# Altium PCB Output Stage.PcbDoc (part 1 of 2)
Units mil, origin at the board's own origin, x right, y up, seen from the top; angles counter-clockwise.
Board outline 5000 x 8750 mil, 6 copper layers (Top Layer, Layer 1, Layer 2, Layer 3, Layer 4, Bottom Layer), stack 91 mil thick; 55 components, 34 nets, 272 pads, 65 vias.
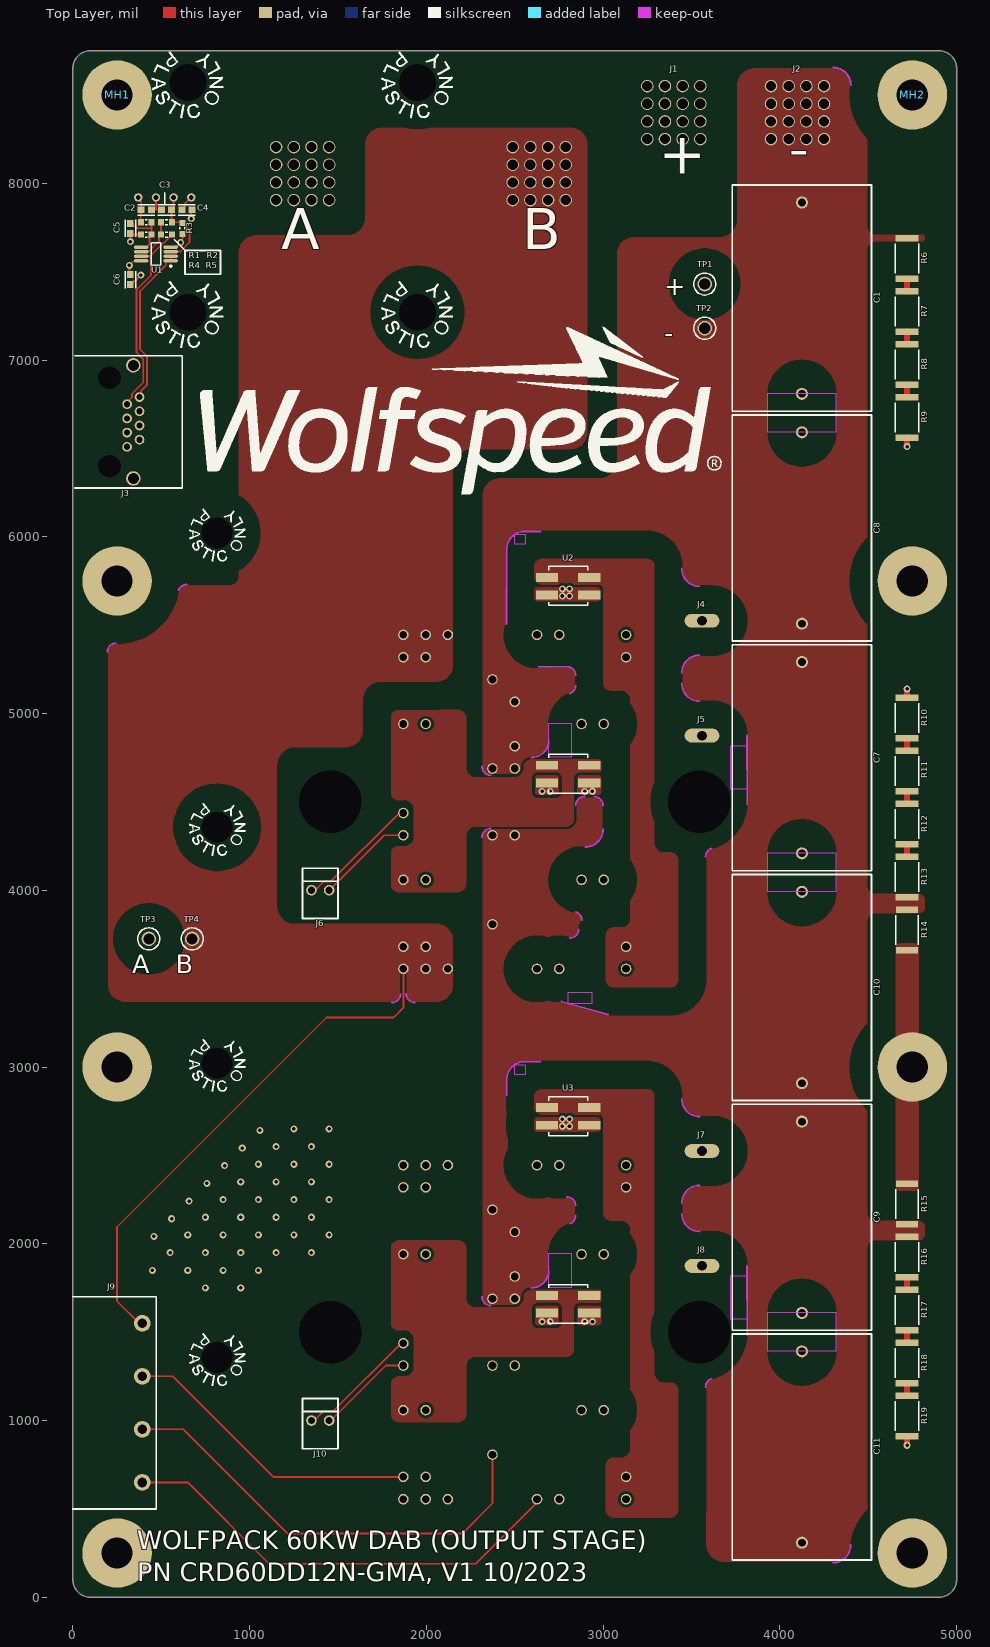
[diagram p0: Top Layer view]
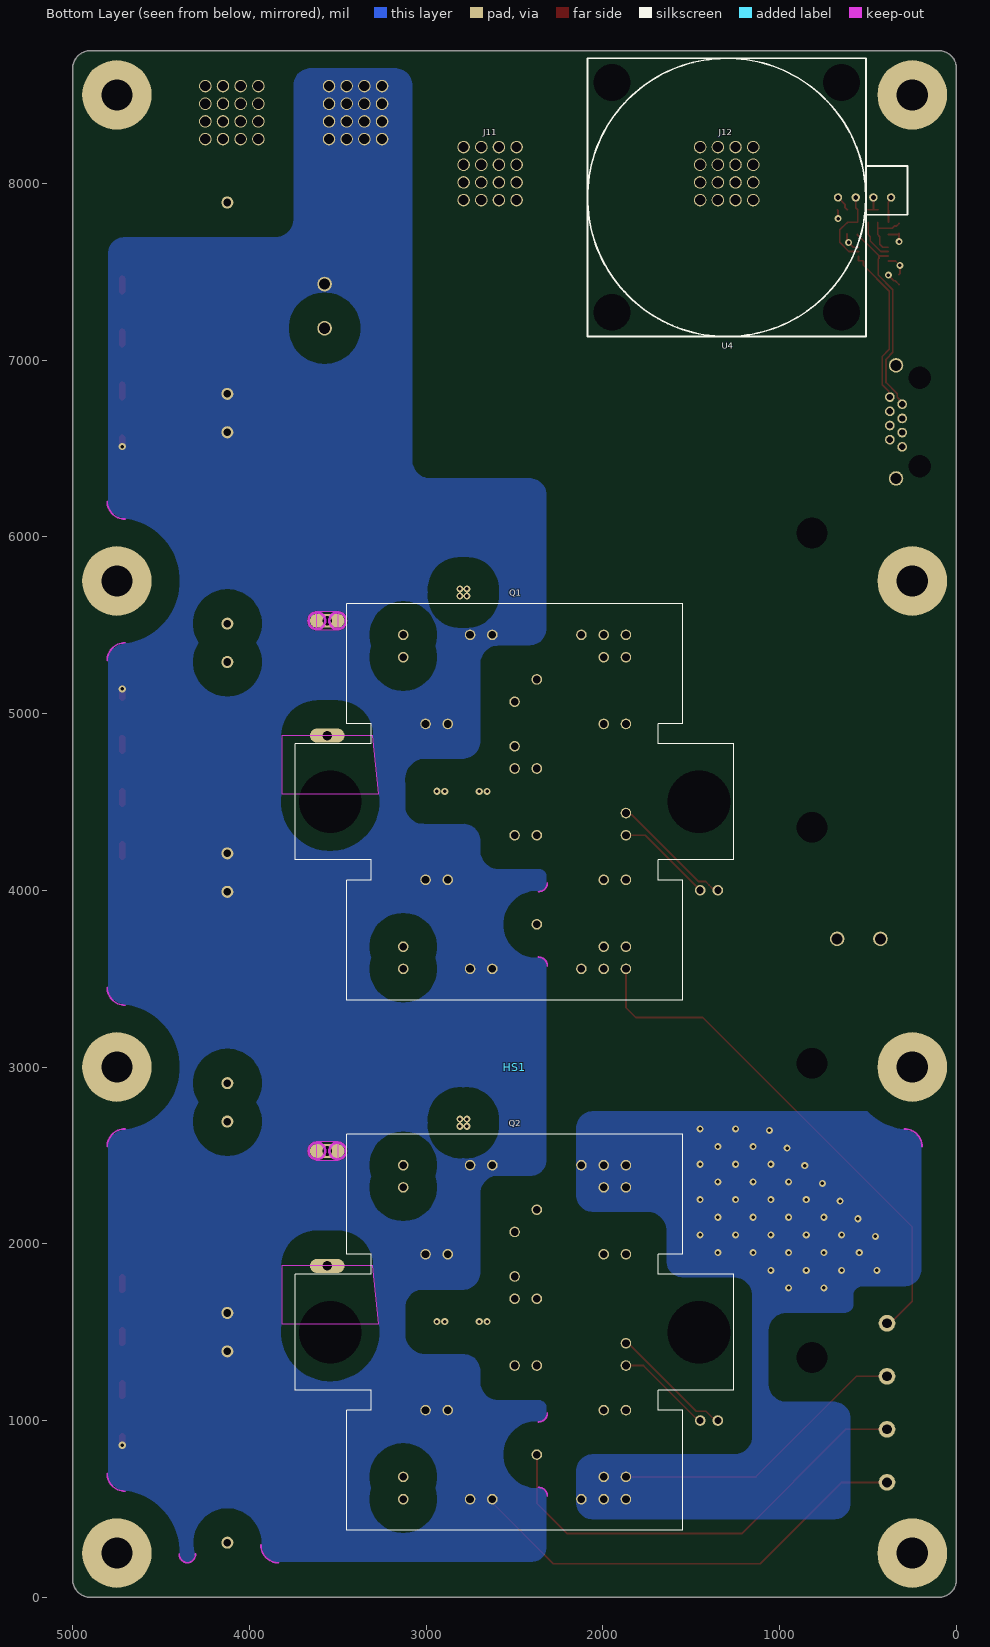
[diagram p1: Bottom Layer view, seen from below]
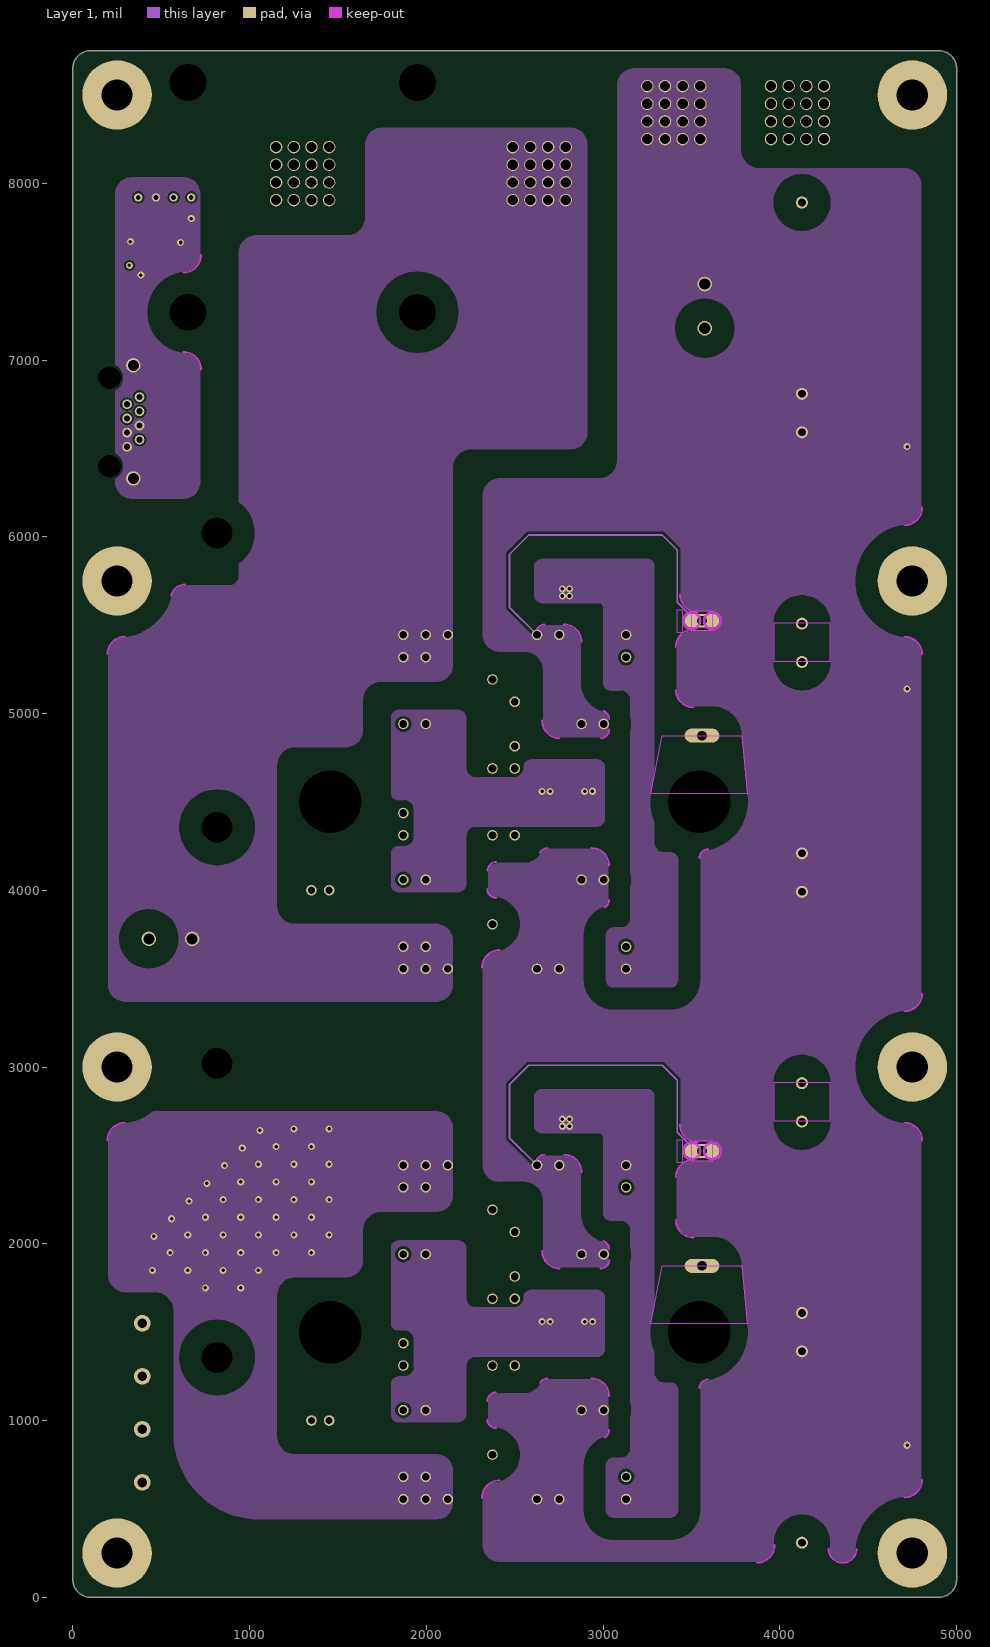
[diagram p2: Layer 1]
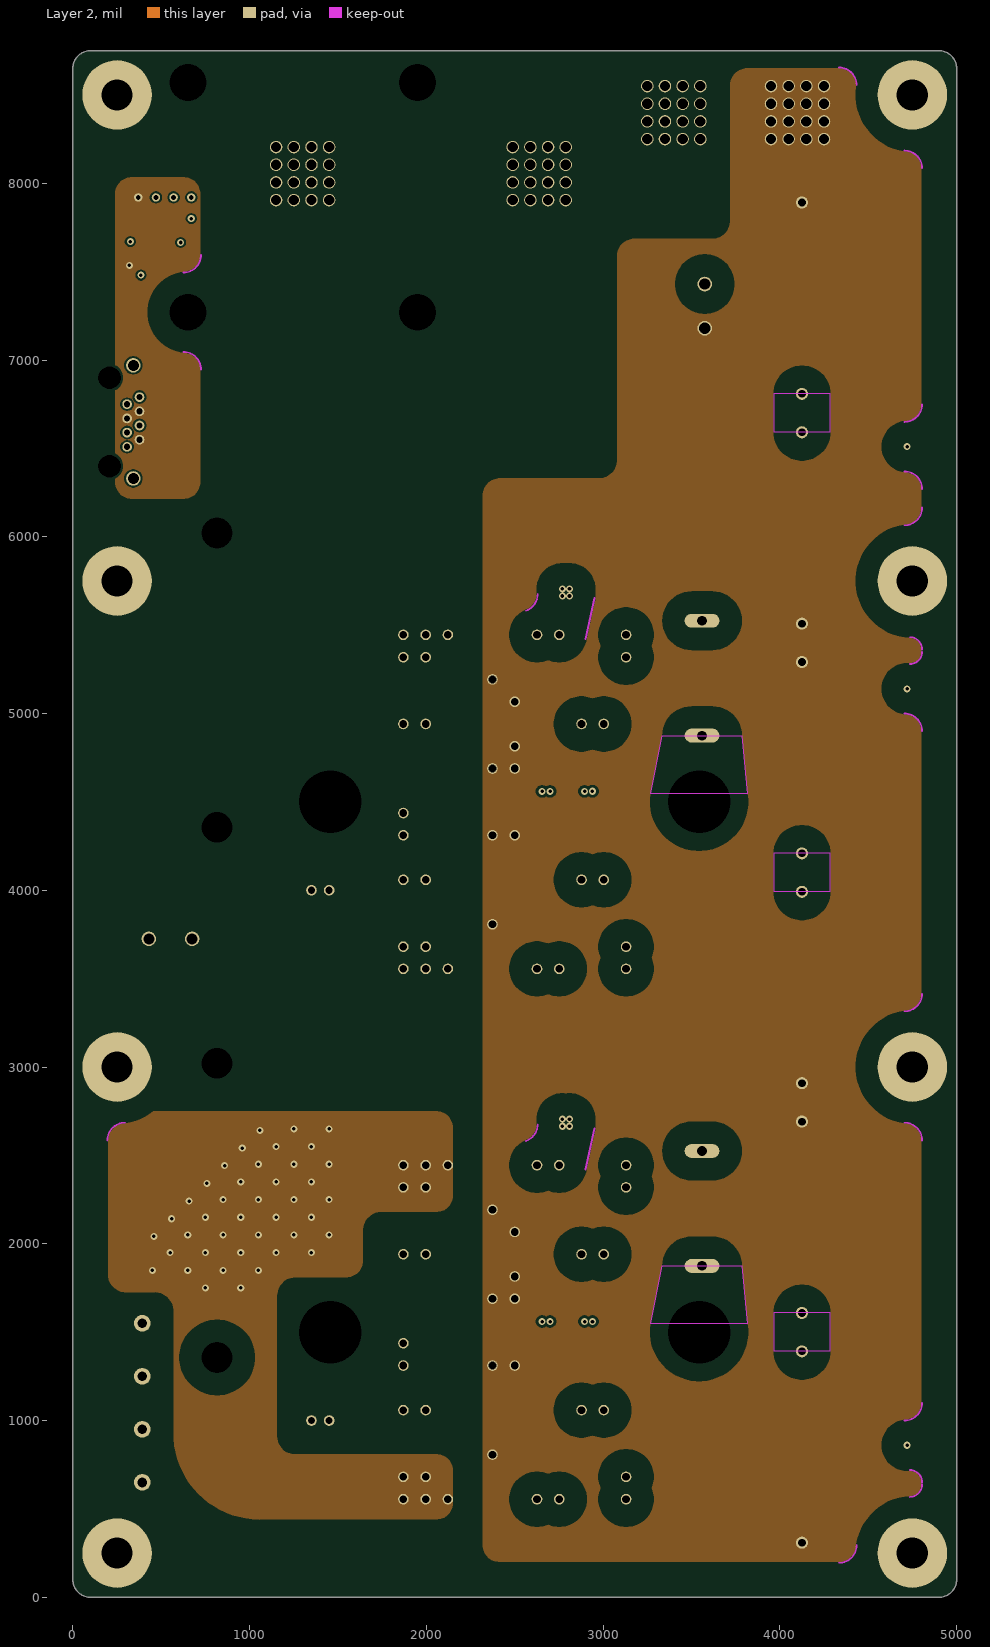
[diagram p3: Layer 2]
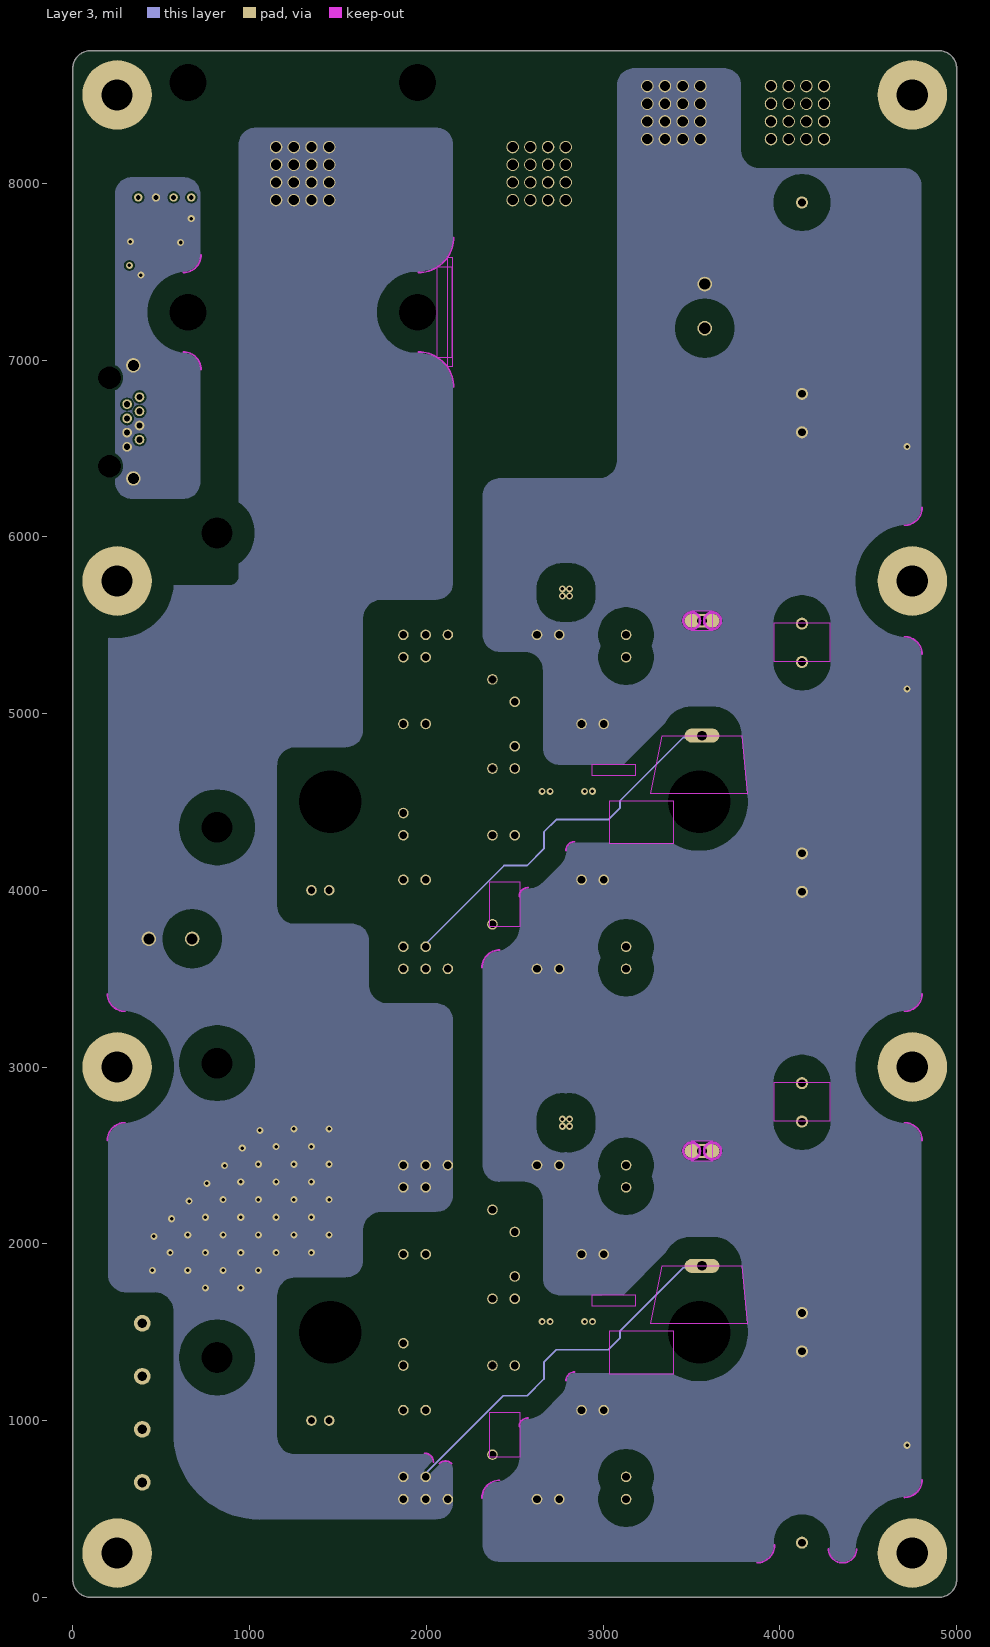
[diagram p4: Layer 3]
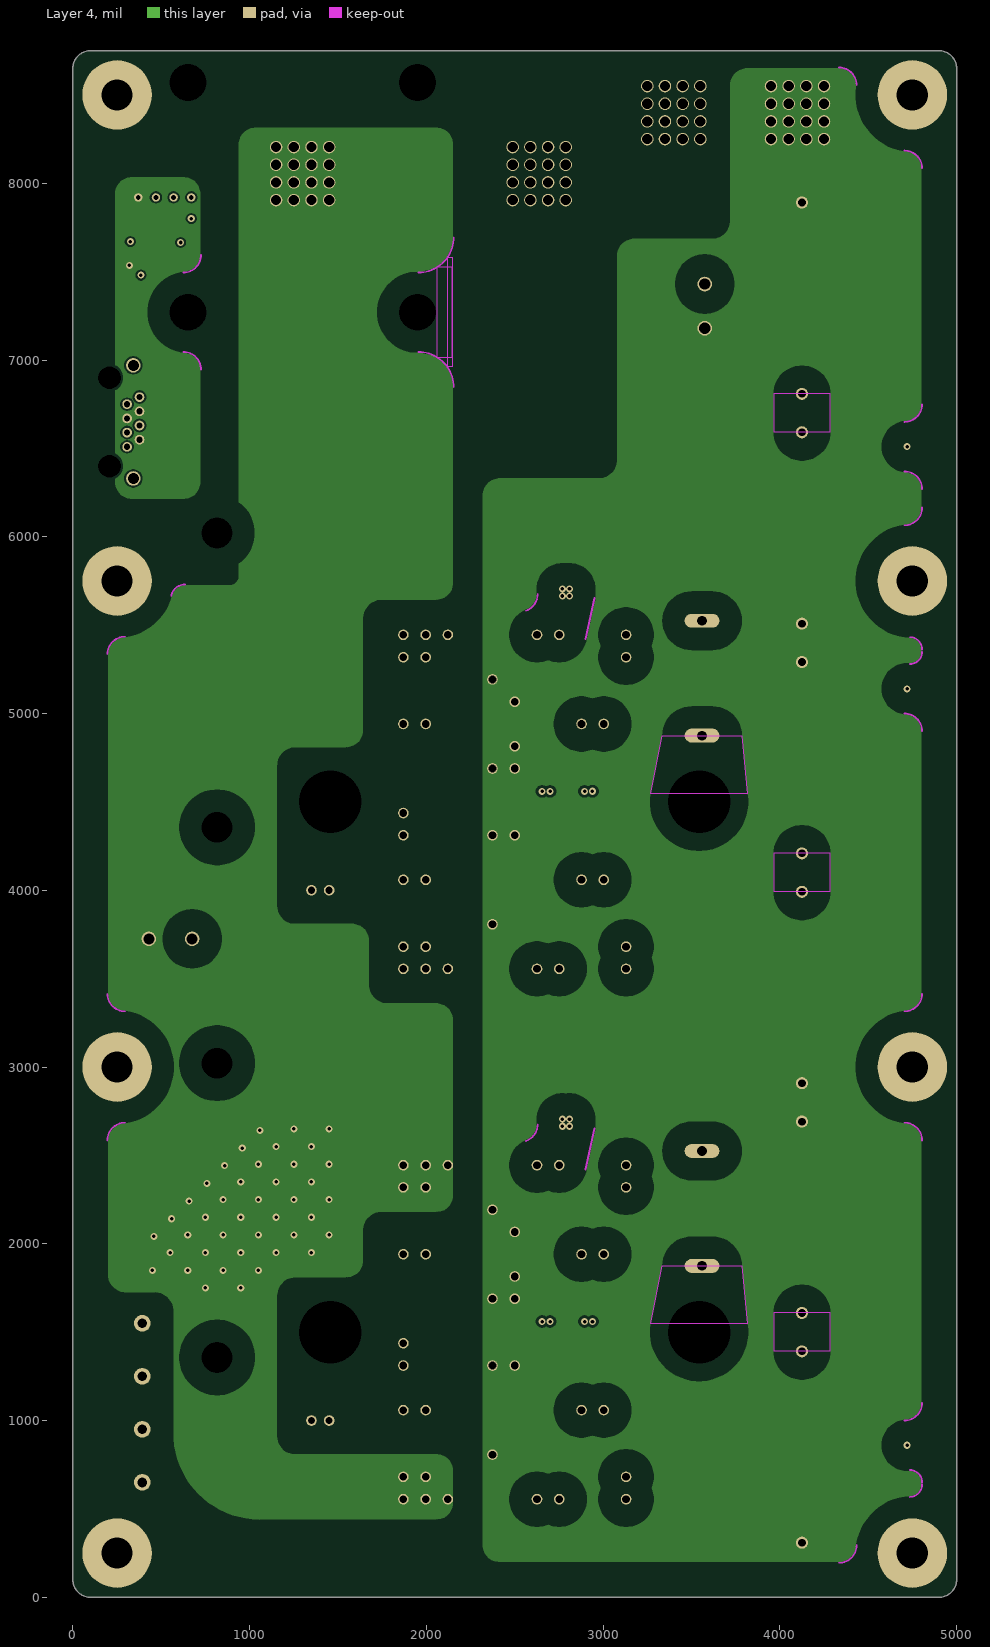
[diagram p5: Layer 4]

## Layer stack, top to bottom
Top Solder: solder mask 1, SM-001, Dk 4
Top Layer: signal copper 8.268
Dielectric 1: prepreg 12.2, PP-006, Dk 4.1
Layer 1: signal copper 8.268
Dielectric 2: prepreg 2.8, PP-006, Dk 4.1
Layer 2: signal copper 8.268
Dielectric 3: dielectric 11.392, FR-4, Dk 4.8
Layer 3: signal copper 8.268
Dielectric 4: prepreg 2.8, PP-006, Dk 4.1
Layer 4: signal copper 8.268
Dielectric 5: prepreg 12.2, PP-006, Dk 4.1
Bottom Layer: signal copper 8.268
Bottom Solder: solder mask 1, SM-001, Dk 4

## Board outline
0,100 0,8650 cw(c100,8650) 100,8750 4900,8750 cw(c4900,8650) 5000,8650 5000,100 cw(c4900,100) 4900,0 100,0 cw(c100,100)

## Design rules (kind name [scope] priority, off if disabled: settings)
Clearance Keepout [IsKeepOut] p1: gap=0 ignorepadtopadclearanceinfootprint=TRUE
Clearance "SENSE CLASS" [InNetClass('SENSE CLASS') vs InNetClass('SENSE CLASS')] p2: gap=10 ignorepadtopadclearanceinfootprint=TRUE except(0: Arc-Hole Track-Hole SMDPad-Hole THPad-Hole Via-Hole Fill-Hole Poly-Hole Region-Hole Text-Hole)
Clearance "A CLASS" [InNetClass('A CLASS') vs InNetClass('A CLASS')] p3: gap=15 ignorepadtopadclearanceinfootprint=TRUE except(0: Arc-Hole Track-Hole SMDPad-Hole THPad-Hole Via-Hole Fill-Hole Poly-Hole Region-Hole Text-Hole)
Clearance "B CLASS" [InNetClass('B CLASS') vs InNetClass('B CLASS')] p4: gap=15 ignorepadtopadclearanceinfootprint=TRUE except(0: Arc-Hole Track-Hole SMDPad-Hole THPad-Hole Via-Hole Fill-Hole Poly-Hole Region-Hole Text-Hole)
Clearance "DC- CLASS" [InNetClass('DC- CLASS') vs InNetClass('DC- CLASS')] p5: gap=15 ignorepadtopadclearanceinfootprint=TRUE except(0: Arc-Hole Track-Hole SMDPad-Hole THPad-Hole Via-Hole Fill-Hole Poly-Hole Region-Hole Text-Hole)
Clearance "DC+ CLASS" [InNetClass('DC+ CLASS') vs InNetClass('DC+ CLASS')] p6: gap=15 ignorepadtopadclearanceinfootprint=TRUE except(0: Arc-Hole Track-Hole SMDPad-Hole THPad-Hole Via-Hole Fill-Hole Poly-Hole Region-Hole Text-Hole)
Clearance "Module Mounting Holes" [HoleDiameter > 350] p7: gap=100 ignorepadtopadclearanceinfootprint=TRUE
Clearance "Ethernet Mounting Holes" [HoleDiameter = 127.953] p8: gap=15 ignorepadtopadclearanceinfootprint=TRUE except(0: Arc-Hole Track-Hole SMDPad-Hole THPad-Hole Via-Hole Fill-Hole Poly-Hole Region-Hole Text-Hole)
Clearance "Internal Clearance" [InLayerClass('InnerLayers')] p9: gap=126 ignorepadtopadclearanceinfootprint=TRUE except(0: Arc-Hole Track-Hole SMDPad-Hole THPad-Hole Via-Hole Fill-Hole Poly-Hole Region-Hole Text-Hole)
Clearance "External Clearance" [All] p10: gap=160 ignorepadtopadclearanceinfootprint=TRUE except(0: Arc-Hole Track-Hole SMDPad-Hole THPad-Hole Via-Hole Fill-Hole Poly-Hole Region-Hole Text-Hole)
Height [All] p1: minheight=0 maxheight=2000 prefheight=500
HoleSize [All] p1: absolutevalues=TRUE maxlimit=500 minlimit=1 maxpercent=80.000 minpercent=20.000
MinimumSolderMaskSliver [All] p1: minsoldermaskwidth=5
PolygonConnect [All] p1: connectstyle=Direct reliefconductorwidth=10 reliefentries=4 polygonreliefangle="90 Angle" airgapwidth=10
RoutingVias [All] p1: holewidth=28 width=50 viastyle="Through Hole" minholewidth=28 minwidth=50 maxholewidth=28 maxwidth=50
SilkToSolderMaskClearance [IsPad] p1: minsilkscreentomaskgap=3.5 clearancetoexposedcopper=TRUE
SolderMaskExpansion [All] p1: expansion=4 istentingtop=FALSE
Width [All] p1: maxlimit=250 minlimit=10 preferedwidth=15
26 further rules are at their usual default settings.

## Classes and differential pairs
net class "SENSE CLASS": +2.5V +5V GND NetC4_1 NetJ10_3 NetJ10_4 NetJ10_5 NetJ10_6 NetR2_2 NetU3_4 OUT_N OUT_P SENSE
net class "DC+ CLASS": DC+
net class "DC- CLASS": DC- G_A_LS G_B_LS NTC_A+ NTC_A- NTC_B+ NTC_B- S_A_LS S_B_LS
net class "B CLASS": AC_B G_B_HS S_B_HS
net class "A CLASS": AC_A G_A_HS S_A_HS

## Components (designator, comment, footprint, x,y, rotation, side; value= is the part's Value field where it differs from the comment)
C1 "C4AQQBU4500A11J" C4AQQBU4500A11J 4125,7350 r90 top value=5μF (schematic designator C6)
C2 "CGA3E3X7S2A473K080AB" FP-C0603C-CF-IPC_B 415,7850 r0 top value=47nF (schematic designator C10)
C3 "C0603C472K5RACAUTO" FP-C0603C-CF-IPC_B 530,7850 r180 top value=4.7nF (schematic designator C9)
C4 "CGA3E3X7S2A473K080AB" FP-C0603C-CF-IPC_B 645,7850 r0 top value=47nF (schematic designator C12)
C5 "CL10B104KB8NNWC" FP-C0603C-CF-IPC_B 325,7745 r270 top value=100nF (schematic designator C11)
C6 "CL10B104KB8NNWC" FP-C0603C-CF-IPC_B 325,7455 r270 top value=100nF (schematic designator C8)
C7 "C4AQQBU4500A11J" C4AQQBU4500A11J 4125,6050 r270 top value=5μF (schematic designator C4)
C8 "C4AQQBU4500A11J" C4AQQBU4500A11J 4125,4750 r90 top value=5μF (schematic designator C5)
C9 "C4AQQBU4500A11J" C4AQQBU4500A11J 4125,3450 r270 top value=5μF (schematic designator C3)
C10 "C4AQQBU4500A11J" C4AQQBU4500A11J 4125,2150 r90 top value=5μF (schematic designator C2)
C11 "C4AQQBU4500A11J" C4AQQBU4500A11J 4125,850 r270 top value=5μF (schematic designator C1)
HS1 "120456" 120456 2500,3000 r90 bottom locked value=N/A
J1 "7461095" "7461095_chemical surface" 3400,8400 r0 top locked value=N/A (schematic designator J4)
J2 "7461095" "7461095_chemical surface" 4100,8400 r0 top locked value=N/A (schematic designator J5)
J3 "2-406541-2" 2-406541-2 207,6650 r270 top value=N/A (schematic designator J10)
J4 "735187-2" 735187-2 3560,5525 r90 top value=N/A (schematic designator J8)
J5 "735187-2" 735187-2 3560,4875 r90 top value=N/A (schematic designator J9)
J6 "0022280021" 0022280021 1400,4000 r0 top locked value=N/A (schematic designator J16)
J7 "735187-2" 735187-2 3560,2525 r90 top value=N/A (schematic designator J6)
J8 "735187-2" 735187-2 3560,1875 r90 top value=N/A (schematic designator J7)
J9 "1728879" 1728879 393,1100 r270 top value=N/A (schematic designator J2)
J10 "0022280021" 0022280021 1400,1000 r0 top locked value=N/A (schematic designator J15)
J11 "7461095" "7461095_chemical surface" 2638.58,8055 r180 bottom locked value=N/A (schematic designator J3)
J12 "7461095" "7461095_chemical surface" 1300,8055 r180 bottom locked value=N/A (schematic designator J1)
MH1 "MH_M4_P" MH_M4_P#1 250,8700 r0 top (schematic designator MH5)
MH2 "MH_M4_P" MH_M4_P#2 4850,8700 r0 top (schematic designator MH3)
Q1 "CAB006M12GM3" GM3_CRW_MH 2500,4500 r90 bottom locked value=N/A (schematic designator Q2)
Q2 "CAB006M12GM3" GM3_CRW_MH 2500,1500 r90 bottom locked value=N/A (schematic designator Q1)
R1 "RG1608P-103-BT5" FP-AC0603-IPC_B 415,7780 r180 top value=10kΩ (schematic designator R4)
R2 "RG1608P-103-BT5" FP-AC0603-IPC_B 530,7780 r180 top value=10kΩ (schematic designator R3)
R3 "RG1608P-103-BT5" FP-AC0603-IPC_B 620,7745 r90 top value=10kΩ (schematic designator R2)
R4 "RG1608P-103-BT5" FP-AC0603-IPC_B 415,7710 r0 top value=10kΩ (schematic designator R5)
R5 "RG1608P-103-BT5" FP-AC0603-IPC_B 530,7710 r0 top value=10kΩ (schematic designator R1)
R6 "CRGP2512F220K" FP-CRGP2512-IPC_C 4720,7575 r90 top value=220kΩ (schematic designator R17)
R7 "CRGP2512F220K" FP-CRGP2512-IPC_C 4720,7275 r90 top value=220kΩ (schematic designator R14)
R8 "CRGP2512F220K" FP-CRGP2512-IPC_C 4720,6975 r90 top value=220kΩ (schematic designator R11)
R9 "CRGP2512F220K" FP-CRGP2512-IPC_C 4720,6675 r90 top value=220kΩ (schematic designator R8)
R10 "CRGP2512F220K" FP-CRGP2512-IPC_C 4720,4975 r270 top value=220kΩ (schematic designator R6)
R11 "CRGP2512F220K" FP-CRGP2512-IPC_C 4720,4675 r270 top value=220kΩ (schematic designator R9)
R12 "CRGP2512F220K" FP-CRGP2512-IPC_C 4720,4375 r270 top value=220kΩ
R13 "CRGP2512F220K" FP-CRGP2512-IPC_C 4720,4075 r270 top value=220kΩ (schematic designator R15)
R14 "RC2512JK-070RL" FP-RC2512-0_65-IPC_C 4720,3775 r270 top value=0Ω (schematic designator R18)
R15 "RC2512JK-070RL" FP-RC2512-0_65-IPC_C 4720,2225 r90 top value=0Ω (schematic designator R19)
R16 "CRGP2512F220K" FP-CRGP2512-IPC_C 4720,1925 r90 top value=220kΩ
R17 "CRGP2512F220K" FP-CRGP2512-IPC_C 4720,1625 r90 top value=220kΩ (schematic designator R13)
R18 "CRGP2512F220K" FP-CRGP2512-IPC_C 4720,1325 r90 top value=220kΩ (schematic designator R10)
R19 "CRGP2512F220K" FP-CRGP2512-IPC_C 4720,1025 r90 top value=220kΩ (schematic designator R7)
TP1 "5010" KSTN-5010_V 3575,7430 r0 top value=RED
TP2 "5011" KSTN-5011_V 3575,7180 r0 top value=BLACK
TP3 "5012" KSTN-5012_V 430,3725 r0 top value=WHITE
TP4 "5014" KSTN-5014_V 675,3725 r0 top value=YELLOW
U1 "AD8616ARMZ-REEL" ADI-RM-8_M 470,7600 r180 top value=N/A (schematic designator U4)
U2 "WolfPack Dual Gate Driver Board Assembly" "WolfPack Dual Gate Driver Board Assembly-Footprint-3" 3000,5190 r90 top locked value=N/A
U3 "WolfPack Dual Gate Driver Board Assembly" "WolfPack Dual Gate Driver Board Assembly-Footprint-3" 3000,2190 r90 top value=N/A (schematic designator U1)
U4 "HTFS200-P/SP2" "HTFS 200-P (No Hole)" 1300,7920 r90 bottom locked value=N/A (schematic designator U3)

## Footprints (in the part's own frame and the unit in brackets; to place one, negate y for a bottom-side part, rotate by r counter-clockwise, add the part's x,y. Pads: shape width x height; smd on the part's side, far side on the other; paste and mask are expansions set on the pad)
2-406541-2 [mm] "CONN MOD JACK R/A 8P8C SHLD"
  round 1.398 hole 0.89: 1(3.58,2.54) 2(2.56,4.32) 3(1.54,2.54) 4(0.52,4.32) 5(-0.5,2.54) 6(-1.52,4.32) 7(-2.54,2.54) 8(-3.56,4.32)
  round 2.087 hole 1.57: 9(8.13,3.43) 10(-8.13,3.43)
  round 0 hole 3.25 unplated: 11(-6.35,0) 11(6.35,0)
  silkscreen extent -9.5,-5 9.5,10.47, body extent -8.13,-5.28 8.13,10.47, height 13.4
120456 [mm]
  round 10 hole 4.5: 1(-69.85,57.15) 2(0,57.15) 3(69.85,57.15) 4(69.85,-57.15) 5(0,-57.15) 6(-69.85,-57.15)
  body extent -127.01,-63.5 101.59,63.5, height 27.24
735187-2 [mm] "CONN QC TAB 0.110 SOLDER"
  oval 2x5 hole 1.4: 1(0,0)
  body extent -0.39,-2.15 0.25,2.15, height 8.62
1728879 [mm] "TERM BLOCK HDR 4POS 90DEG 7.62MM"
  round 2.4 hole 1.4: 1(-11.43,0) 2(-3.81,0) 3(3.81,0) 4(11.43,0)
  silkscreen extent -15.24,-10 15.24,2, body extent -15.24,-10 15.19,2, height 8.57
"7461095_chemical surface" [mm] "M4, blind 4mm"
  round 1.8 hole 1.475: 1(-3.81,-3.81) 1(-3.81,-1.27) 1(-3.81,1.27) 1(-3.81,3.81) 1(-1.27,-3.81) 1(-1.27,-1.27) 1(-1.27,1.27) 1(-1.27,3.81) 1(1.27,-3.81) 1(1.27,-1.27) 1(1.27,1.27) 1(1.27,3.81) 1(3.81,-3.81) 1(3.81,-1.27) 1(3.81,1.27) 1(3.81,3.81)
  body extent -4.5,-4.5 4.5,4.5, height 7
0022280021 [mil] "CONN HEADER VERT 2POS 2.54MM"
  round 60 hole 40.16: 1(-50,0) 2(50,0)
  silkscreen extent -100,-160 100,124, body extent -100,-160 100,124, height 422
ADI-RM-8_M [mm] "SOP, 8-Leads, Body 3x3mm, Pitch 0.65mm, IPC Low Density"
  oval 2.1x0.45 smd: 1(-2.125,0.975) 2(-2.125,0.325) 3(-2.125,-0.325) 4(-2.125,-0.975) 5(2.125,-0.975) 6(2.125,-0.325) 7(2.125,0.325) 8(2.125,0.975)
  silkscreen extent -2.25,-1.6 0.67,1.87, body extent -1.6,-1.6 1.6,1.6, height 1.1
C4AQQBU4500A11J [mm]
  round 1.735 hole 1.1: 1(-13.75,0) 2(13.75,0)
  silkscreen extent -16.25,-10 16.25,10, body extent -16,-9.65 16,9.65, height 29.2
FP-AC0603-IPC_B [mil]
  rect 33.81x35.91 smd paste+0 mask+0: 1(-30.58,0) 2(30.58,0)
  silkscreen extent -6,-14 6,14, body extent -31,-18 31,18, height 20
FP-C0603C-CF-IPC_B [mil]
  rect 39.63x37.73 smd paste+0 mask+0: 1(-28.58,0) 2(28.58,0)
  silkscreen extent -48,-30 48,30, body extent -58,-29 58,29, height 35
FP-CRGP2512-IPC_C [mil]
  rect 37.72x130.17 smd paste+0 mask+0: 1(-114.25,0) 2(114.25,0)
  silkscreen extent -84,-67 84,67, body extent -137,-71 137,71, height 10
FP-RC2512-0_65-IPC_C [mil]
  rect 37.72x124.34 smd paste+0 mask+0: 1(-114.25,0) 2(114.25,0)
  silkscreen extent -84,-64 84,64, body extent -137,-68 137,68, height 10
GM3_CRW_MH [mm]
  round 0 hole 9 unplated: 2(0,-26.5) 2(0,26.5)
  round 1.524 hole 1.1: AC_1(-24,-9.6) AC_2(24,-9.6) AC_3(-24,-12.8) AC_4(-20.8,-12.8) AC_5(20.8,-12.8) AC_6(24,-12.8) AC_7(-24,-16) AC_8(-20.8,-16) AC_9(20.8,-16) AC_10(24,-16) DC+_1(-11.2,12.8) DC+_2(11.2,12.8) DC+_3(-11.2,9.6) DC+_4(11.2,9.6) DC+_5(-24,6.4) DC+_6(24,6.4) DC+_7(-24,3.2) DC+_8(24,3.2) DC-_1(-4.8,0) DC-_2(4.8,0) DC-_3(8,0) DC-_4(14.4,0) DC-_5(-17.6,-3.2) DC-_6(-4.8,-3.2) DC-_7(4.8,-3.2) DC-_8(17.6,-3.2) G1_1(-20.8,16) G1_2(20.8,16) G2_1(-11.2,-16) G2_2(11.2,-16) NTC1(-4.8,-16) NTC2(-1.6,-16) S1_1(-24,16) S1_2(24,16) S2_1(-11.2,-12.8) S2_2(11.2,-12.8)
  silkscreen extent -28.47,-31.52 28.47,31.52, body extent -28.35,-31.4 28.35,31.4, height 12.08
"HTFS 200-P (No Hole)" [mm]
  round 1.208 hole 0.7: 1(0,-23.62) 2(0,-21.08) 3(0,-18.54) 4(0,-16)
  round 0 hole 5.3 unplated: MH1(-16.5,16.5) MH2(16.5,16.5) MH3(16.5,-16.5) MH4(-16.5,-16.5)
  silkscreen extent -20,-26 20,20, body extent -20,-26 20,20, height 16.5
KSTN-5010_V [mm] "Test Point, Dia 3.17mm"
  round 2.1 hole 1.6: 1(0,0)
  silkscreen extent -1.59,-1.58 1.59,1.58, body extent -1.59,-1.59 1.59,1.59, height 8.13
KSTN-5011_V [mm] "Test Point, Dia 3.17mm"
  round 2.1 hole 1.6: 1(0,0)
  silkscreen extent -1.59,-1.58 1.59,1.58, body extent -1.59,-1.59 1.59,1.59, height 8.13
KSTN-5012_V [mm] "Test Point, Dia 3.17mm"
  round 2.1 hole 1.6: 1(0,0)
  silkscreen extent -1.59,-1.58 1.59,1.58, body extent -1.59,-1.59 1.59,1.59, height 8.13
KSTN-5014_V [mm] "Test Point, Dia 3.17mm"
  round 2.1 hole 1.6: 1(0,0)
  silkscreen extent -1.59,-1.58 1.59,1.58, body extent -1.59,-1.59 1.59,1.59, height 8.13
MH_M4_P#1 [mm] "M4 plated mounting hole"
  round 10 hole 4.5: 1(0,-5.08)
MH_M4_P#2 [mm] "M4 plated mounting hole"
  round 10 hole 4.5: 1(-2.54,-5.08)
"WolfPack Dual Gate Driver Board Assembly-Footprint-3" [mil]
  rect 50x125 smd: 1A(480.53,316.96) 1B(-582.47,316.96) 2A(580.53,316.96) 2B(-482.47,316.96) 3A(480.53,78.46) 3B(-582.47,78.46) 4A(580.53,78.46) 4B(-482.47,78.46)
  round 0 hole 175 unplated: A46(-833.49,2183.63) A46(831.55,2183.63)
  silkscreen extent -641,86 642,306, body extent -1237,15 1000,2365, height 951

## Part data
C1 C7 C8 C9 C10 C11: "CAP FILM 5UF 5% 1.1KVDC RADIAL", Capacitance=5μF, Case/Package=RADIAL, Dielectric Material=PP, ESR (Equivalent Series Resistance)=9.1mR, Manufacturer=KEMET, Max Operating Temperature=105°C, Min Operating Temperature=-40°C, Ratings=AEC-Q200, Supplier Part Number 1=80-C4AQQBU4500A11J, TOLERANCE=5%, Voltage Rating (DC)=1.1kV
C2 C4: "CAP CER 0.047UF 100V X7S 0603", Case Code (Imperial)=0603, Case Code (Metric)=1608, Dielectric=X7S, Manufacturer=TDK, Max Operating Temperature=125°C, Min Operating Temperature=-55°C, Package Quantity=4000, Ratings=AEC-Q200, TOLERANCE=10%, Voltage Rating=100V
C3: library part CMP-001-00119-9, "CAP CER 4700PF 50V X7R 0603", Capacitor Type=Ceramic, Case/Package=0603, Manufacturer=KEMET, Max Operating Temperature=125°C, Min Operating Temperature=-55°C, Temperature Coefficient=X7R, TOLERANCE=10%, Voltage Rating=50V
C5 C6: library part CMP-00017-3, "CAP CER 0.1UF 50V X7R 0603", Capacitor Type=Ceramic, Case/Package=0603, Manufacturer=SAMSUNG, Max Operating Temperature=125°C, Min Operating Temperature=-55°C, Temperature Coefficient=X7R, TOLERANCE=10%, Voltage Rating=50V
HS1: "COLD PLATE HEAT SINK EXPOSED", Case/Package=N/A, Manufacturer=WAKEFIELD, Supplier Part Number 1=345-1425-ND
J1 J2 J11 J12: library part CMP-03913-18187404-1, "TERM REDCUBE M4 16PIN PCB", Case/Package=N/A, Current Rating=180A, Manufacturer=WURTH, Max Operating Temperature=150°C, Min Operating Temperature=-55°C
J3: "CONN MOD JACK R/A 8P8C SHLD", Case/Package=N/A, Manufacturer=TE
J4 J5 J7 J8: "CONN QC TAB 0.110 SOLDER", Case/Package=N/A, Manufacturer=TE
J6 J10: "CONN HEADER VERT 2POS 2.54MM", Case/Package=N/A, Manufacturer=MOLEX, Supplier Part Number 1=WM19476-ND
J9: "TERM BLOCK HDR 4POS 90DEG 7.62MM", Case/Package=N/A, Manufacturer="PHEONIX CONTACT"
Q1 Q2: "SIC 2N-CH 1200V", Case/Package=GMA, Manufacturer=WOLFSPEED
R1 R2 R3 R4 R5: library part CMP-009-00206-2, "RES SMD 10K OHM 0.1% 1/10W 0603", Case/Package=0603, Manufacturer=SUSUMU, Manufacturer Part Number=RG1608P-103-B-T5, Max Operating Temperature=155°C, Min Operating Temperature=-55°C, POWER=0.1W, TOLERANCE=0.1%, Voltage Rating=75V
R6 R8 R9 R10 R11 R12 R13 R16 R17 R18 R19: library part CMP-03211-002966-1, "RES 220K OHM 1% 2W 2512", Ambient Temperature Range High=+70°C, Case/Package=2512, Manufacturer=TE, Power Rating=2W, Resistance=220KΩ, Temperature="-55°C to +155°C", Temperature Coefficient=±100ppm/°C, Temperature Range High=+155°C, Temperature Range Low=-55°C, TOLERANCE=0.01, Voltage Rating=500V
R7: library part CMP-03211-002966-1, "CRGP2512 220KΩ 2W ±100ppm/°C 1% 500V", Ambient Temperature Range High=+70°C, Case/Package=2512, Manufacturer=TE, Power Rating=2W, Resistance=220KΩ, Temperature="-55°C to +155°C", Temperature Coefficient=±100ppm/°C, Temperature Range High=+155°C, Temperature Range Low=-55°C, TOLERANCE=0.01, Voltage Rating=500V
R14 R15: library part CMP-2000-06974-2, "RES SMD 0 OHM JUMPER 1W 2512", Case Code (Imperial)=2512, Case Code (Metric)=6432, Manufacturer=YAGEO, Max Operating Temperature=155°C, Max Power Dissipation=1W, Min Operating Temperature=-55°C, Package Quantity=4000, Resistance=0Ω, Resistance Tolerance=5%, Resistor Type="Thick Film", Temperature Coefficient=200ppm/°C, Voltage Rating=200V
TP1: library part CMP-1672-00002-4, "PC TEST POINT MULTIPURPOSE RED", Case/Package=N/A, Colour=Red, Manufacturer=KEYSTONE, Package Quantity=100
TP2: library part CMP-1672-00003-4, "PC TEST POINT MULTIPURPOSE BLACK", Case/Package=N/A, Colour=Black, Manufacturer=KEYSTONE, Package Quantity=100
TP3: library part CMP-1672-00004-4, "PC TEST POINT MULTIPURPOSE WHITE", Case/Package=N/A, Colour=White, Manufacturer=KEYSTONE, Package Quantity=100
TP4: library part CMP-1672-00006-4, "PC TEST POINT MULTI PURP YELLOW", Case/Package=N/A, Colour=Yellow, Manufacturer=KEYSTONE, Package Quantity=100
U1: library part CMP-0384-01706-1, "IC CMOS 2 CIRCUIT 8MSOP", Amplifiers Per Package=2, Case/Package=8-TSSOP, Generic Part Number=AD8616, Input Bias Current=200fA, Input Offset Voltage=23uV, Manufacturer=ANALOG
U2 U3: library part CMP-00030-00001-20, "GATE DRIVER BOARD 1700V CAPABLE", Case/Package=N/A, Manufacturer=WOLFSPEED, Manufacturer Part Number=CGD1700HB2M-UNA
U4: library part "HTFS 200-P", "SENSOR CURRENT HALL 200A AC/DC", Case/Package=N/A, Flammability Rating="UL94 V-0", Manufacturer=LEM, Max Operating Temperature=105°C, Max Supply Voltage (DC)=5.25V, Min Operating Temperature=-40°C, Min Supply Voltage (DC)=4.75V, Operating Supply Voltage=5V, Supplier Part Number 1=97K1712

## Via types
v1: diameter 40, hole 20, Top Layer to Bottom Layer, tented both sides, 65 vias

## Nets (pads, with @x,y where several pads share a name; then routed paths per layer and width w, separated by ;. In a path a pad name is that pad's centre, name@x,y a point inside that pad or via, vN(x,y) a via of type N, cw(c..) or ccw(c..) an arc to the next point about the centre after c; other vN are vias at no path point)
+2.5V: C5.1 R1.1 R4.2 U1.5 | length 316.9
  Top Layer w10: C5.1@325,7773.58 325,7772.63 338.86,7758.76 349.58,7758.76 363.35,7745 445.58,7745 ; U1.5@386.34,7638.39 416.73,7638.39 433.68,7655.33 433.68,7698.1 R4.2@445.58,7710 445.58,7745 ; R1.1@445.58,7780 445.58,7745
+5V: C2.1 C6.1 J3.2 J3.5 J3.6 R1.2 U1.8 U4.1 | length 278.5
  Top Layer w10: C6.1@325,7483.58 320,7488.58 v1(320,7535) 345.14,7560.14 384.86,7560.14 U1.8@386.34,7561.61 ; U4.1@370.08,7920 370.08,7909.84 386.42,7893.49 C2.1@386.42,7850 384.42,7848 R1.2@384.42,7780
AC_A: J8.1 J9.2 J12.1 Q2.AC_1 Q2.AC_2 Q2.AC_3 Q2.AC_4 Q2.AC_5 Q2.AC_6 Q2.AC_7 Q2.AC_8 Q2.AC_9 Q2.AC_10 TP3.1 | length 3863.6
  Top Layer w10: J9.2@393,1250 565.79,1250 1134.69,681.1 Q2.AC_8@1870.08,681.1
  Layer 3 w10: Q2.AC_4@1996.06,681.1 2005.63,690.67 2005.63,710.63 2435,1140 2570,1140 2665,1235 2665,1330 2735,1400 3030,1400 3095,1465 3095,1505 3454.53,1864.53 3549.53,1864.53 ccw(c3549.53,1875) J8.1@3560,1875
  other v1: 750,1750 950,1750 450,1850 650,1850 850,1850 1050,1850 550,1950 750,1950 950,1950 1150,1950 1350,1950 458.31,2041.69 650,2050 850,2050 1050,2050 1250,2050 1450,2050 558.31,2141.69 750,2150 950,2150 1150,2150 1350,2150 658.31,2241.69 850,2250 1050,2250 1250,2250 1450,2250 758.31,2341.69 950,2350 1150,2350 1350,2350 858.31,2441.69 1050,2450 1250,2450 1450,2450 958.31,2541.69 1150,2550 1350,2550 1058.31,2641.69 1250,2650 1450,2650
AC_B: J5.1 J9.1 J11.1 Q1.AC_1 Q1.AC_2 Q1.AC_3 Q1.AC_4 Q1.AC_5 Q1.AC_6 Q1.AC_7 Q1.AC_8 Q1.AC_9 Q1.AC_10 TP4.1 | length 5100.1
  Top Layer w10: J9.1@393,1550 375,1550 250,1675 250,2095 1435,3280 1815,3280 1870,3335 1870,3555.04 Q1.AC_7@1870.08,3555.12
  Layer 3 w10: Q1.AC_4@1996.06,3681.1 1996.06,3694.63 2010.4,3708.97 2010.4,3710.4 2440,4140 2570,4140 2665,4235 2665,4330 2735,4400 3030,4400 3095,4465 3095,4505 3454.53,4864.53 J5.1@3549.53,4864.53
DC+: C1.1 C7.1 C8.1 C9.1 C10.1 C11.1 J1.1 J4.1 J7.1 J9.4 Q1.DC+_1 Q1.DC+_2 Q1.DC+_3 Q1.DC+_4 Q1.DC+_5 Q1.DC+_6 Q1.DC+_7 Q1.DC+_8 Q2.DC+_1 Q2.DC+_2 Q2.DC+_3 Q2.DC+_4 Q2.DC+_5 Q2.DC+_6 Q2.DC+_7 Q2.DC+_8 R9.1 R10.1 R19.1 TP1.1 | length 6802.8
  Top Layer w10: J9.4@393,650 650,650 1110,190 2280.42,190 2616.42,526 2616.42,545.55 Q2.DC+_7@2625.98,555.12
  Top Layer w35: v1(4720,860) R19.1@4720,910.75 ; R10.1@4720,5089.25 v1(4720,5140) ; v1(4720,6510) R9.1@4720,6560.75
  Layer 1 w10: Q2.DC+_8@2625.98,2444.88 2470,2600.87 2470,2900 2580,3010 3335,3010 3420,2925 3420,2630 3487.79,2562.21 3487.79,2556.75 3519.55,2525 J7.1@3560,2525 ; Q1.DC+_8@2625.98,5444.88 2470,5600.87 2470,5900 2580,6010 3335,6010 3420,5925 3420,5630 3487.79,5562.21 3487.79,5556.75 3519.55,5525 J4.1@3560,5525
DC-: C1.2 C7.2 C8.2 C9.2 C10.2 C11.2 J2.1 J9.3 Q1.DC-_1 Q1.DC-_2 Q1.DC-_3 Q1.DC-_4 Q1.DC-_5 Q1.DC-_6 Q1.DC-_7 Q1.DC-_8 Q2.DC-_1 Q2.DC-_2 Q2.DC-_3 Q2.DC-_4 Q2.DC-_5 Q2.DC-_6 Q2.DC-_7 Q2.DC-_8 R6.2 R13.2 R14.1 R15.1 R16.2 TP2.1 | length 2572
  Top Layer w10: J9.3@393,950 625.38,950 1215.26,360.12 2202.82,360.12 2374.02,531.31 Q2.DC-_5@2374.02,807.09
EGND: HS1.2 R14.2 R15.2
G_A_HS: Q2.G1_1 Q2.G1_2 U3.2A U3.4A
G_A_LS: Q2.G2_1 Q2.G2_2 U3.2B U3.4B
G_B_HS: Q1.G1_1 Q1.G1_2 U2.2A U2.4A
G_B_LS: Q1.G2_1 Q1.G2_2 U2.2B U2.4B
GND: C2.2 C3.2 C4.2 C5.2 C6.2 J3.1 J3.3 J3.4 J3.9 J3.10 R3.1 R4.1 U1.4 U4.2 | length 493.3
  Top Layer w10: C6.2@325,7426.42 325,7427.37 346.39,7448.76 353.76,7448.76 v1(385,7480) ; v1(325,7670) C5.2@325,7716.42 331.42,7710 R4.1@384.42,7710 ; C2.2@443.58,7850 472.5,7850 ; U4.2@470.08,7920 470.08,7852.42 472.5,7850 ; C3.2@501.42,7850 472.5,7850 ; U1.4@553.66,7638.39 584.76,7638.39 610,7663.62 v1(610,7665) 610,7673.12 620,7683.12 R3.1@620,7714.42 ; v1(670,7800) 670,7846.42 C4.2@673.58,7850
NetC4_1: C4.1 U4.4 | length 92.8
  Top Layer w10: C4.1@616.42,7850 617.37,7850 631.24,7863.86 631.24,7881.16 U4.4@670.08,7920
NetR2_2: R2.2 R5.1 U1.6 | length 237.8
  Top Layer w10: U1.6@386.34,7612.8 387.82,7614.27 428.45,7614.27 487.52,7673.34 487.52,7698.1 R5.1@499.42,7710 R2.2@499.42,7780
NetR6_1: R6.1 R7.2 | length 71.5
  Top Layer w35: R7.2@4720,7389.25 R6.1@4720,7460.75
NetR7_1: R7.1 R8.2 | length 71.5
  Top Layer w35: R8.2@4720,7089.25 R7.1@4720,7160.75
NetR8_1: R8.1 R9.2 | length 71.5
  Top Layer w35: R9.2@4720,6789.25 R8.1@4720,6860.75
NetR10_2: R10.2 R11.1 | length 71.5
  Top Layer w35: R11.1@4720,4789.25 R10.2@4720,4860.75
NetR11_2: R11.2 R12.1 | length 71.5
  Top Layer w35: R12.1@4720,4489.25 R11.2@4720,4560.75
NetR12_2: R12.2 R13.1 | length 71.5
  Top Layer w35: R13.1@4720,4189.25 R12.2@4720,4260.75
NetR16_1: R16.1 R17.2 | length 71.5
  Top Layer w35: R17.2@4720,1739.25 R16.1@4720,1810.75
NetR17_1: R17.1 R18.2 | length 71.5
  Top Layer w35: R18.2@4720,1439.25 R17.1@4720,1510.75
NetR18_1: R18.1 R19.2 | length 71.5
  Top Layer w35: R19.2@4720,1139.25 R18.1@4720,1210.75
NTC_A+: J10.2 Q2.NTC1 | length 548.9
  Top Layer w10: J10.2@1450,1000 1460,1000 1771.02,1311.02 Q2.NTC1@1870.08,1311.02
NTC_A-: J10.1 Q2.NTC2 | length 701.1
  Top Layer w10: J10.1@1350,1000 1363.53,1000 1377.85,1014.32 1379.32,1014.32 1417,1052 1472,1052 1857.01,1437.01 Q2.NTC2@1870.08,1437.01
NTC_B+: J6.2 Q1.NTC1 | length 548.9
  Top Layer w10: J6.2@1450,4000 1761.02,4311.02 Q1.NTC1@1870.08,4311.02
NTC_B-: J6.1 Q1.NTC2 | length 701.1
  Top Layer w10: J6.1@1350,4000 1359.57,4009.57 1379.57,4009.57 1400,4030 1420,4050 1460,4050 1837.44,4427.44 1860.51,4427.44 Q1.NTC2@1870.08,4437.01
OUT_N: J3.7 R5.2 U1.7 | length 1154.2
  Top Layer w10: J3.7@307,6750 307,6762.19 334.56,6789.75 334.56,6809.56 398.12,6873.12 398.12,7005 360,7043.12 360,7398.28 442.68,7480.96 442.68,7571.5 437.74,7576.44 437.74,7588.68 ; U1.7@386.34,7587.2 387.82,7588.68 437.74,7588.68 ; R5.2@560.58,7710 560.58,7708.95 513.87,7662.24 511.3,7662.24 437.74,7588.68
OUT_P: J3.8 U1.1 U1.2 | length 917.3
  Top Layer w10: J3.8@377.08,6790.16 383.68,6796.76 383.68,6823.68 420,6860 420,7020 380,7060 380,7390 526.18,7536.18 526.18,7558.05 529.75,7561.61 U1.1@553.66,7561.61 U1.2@553.66,7587.2
S_A_HS: Q2.S1_1 Q2.S1_2 U3.1A U3.3A
  other v1: 2770,2665 2810,2665 2770,2705 2810,2705
S_A_LS: Q2.S2_1 Q2.S2_2 U3.1B U3.3B
  other v1: 2655,1560 2700,1560 2895,1560 2940,1560
S_B_HS: Q1.S1_1 Q1.S1_2 U2.1A U2.3A
  other v1: 2770,5665 2810,5665 2770,5705 2810,5705
S_B_LS: Q1.S2_1 Q1.S2_2 U2.1B U2.3B
  other v1: 2655,4560 2700,4560 2895,4560 2939.66,4560.34
SENSE: C3.1 R2.1 R3.2 U1.3 U4.3 | length 462.3
  Top Layer w10: U1.3@553.66,7612.8 555.14,7614.27 608.77,7614.27 660,7665.5 660,7736.63 621.05,7775.58 R3.2@620,7775.58 615.58,7780 R2.1@560.58,7780 558.58,7782 C3.1@558.58,7850 570.08,7861.5 U4.3@570.08,7920
pads on no net: HS1.1 HS1.3 HS1.4 HS1.5 HS1.6 J3.11 MH1.1 MH2.1 Q1.2 Q2.2 U2.A46 U3.A46 U4.MH1 U4.MH2 U4.MH3 U4.MH4

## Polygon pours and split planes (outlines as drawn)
DC- on Top Layer "NONET_L-01_P-001" (solid, pour order 50): 2320,1700 ccw(c2364.71,1700) 2364.71,1655.29 3485,1655.29 cw(c3485,1555.3) 3585,1555.29 3585,300 ccw(c3685,300) 3685,200 4400,200 ccw(c4400,295) 4495,295 4495,325 4495,1975 cw(c4539.99,1975) 4540,2020 4785,2020 ccw(c4785,2055) 4820,2055 4820,2095 ccw(c4785.01,2095) 4785,2130 4540,2130 cw(c4539.04,2174.04) 4495,2175 4495,3825 cw(c4539.99,3825.01) 4540,3870 4785,3870 ccw(c4785,3905) 4820,3905 4820,3945 ccw(c4785,3945) 4785,3980 4540,3980 cw(c4539.99,4024.99) 4495,4025 4495,7625 cw(c4539.99,7625.01) 4540,7670 4805,7670 ccw(c4805,7685) 4820,7685 4820,7695 ccw(c4805,7695) 4805,7710 4540,7710 cw(c4539.99,7754.99) 4495,7755 4495,8555 ccw(c4400.01,8555.01) 4400,8650 3890,8650 3855,8650 ccw(c3854.98,8555.02) 3760,8555 3760,7800 cw(c3654.92,7800.08) 3655,7695 3175,7695 ccw(c3174.98,7600.02) 3080,7600 3080,6434.06 cw(c2975.96,6434.04) 2975.95,6330 2415,6330 ccw(c2414.98,6235.02) 2320,6235
G_A_LS on Top Layer "NONET_L-01_P-001" (solid, pour order 49): 2549.99,1694.99 cw(c2594.98,1694.99) 2595,1740 2975,1740 cw(c2972.51,1722.51) 2990,1720 2990,1680 cw(c2975.01,1679.99) 2975,1665 2865,1665 ccw(c2864.99,1635.01) 2835,1635 2835,1405 cw(c2790.01,1404.99) 2790,1360 2279.71,1360 ccw(c2279.69,1305.31) 2225,1305.29 2225,1035 cw(c2178.67,1036.33) 2180,990 1865,990 1845,990 cw(c1844.99,1034.99) 1800,1035 1800,1205 cw(c1845,1205) 1845,1250 1874.71,1250 ccw(c1874.71,1305.29) 1930,1305.29 1930,1315 1930,1457.27 ccw(c1874.66,1454.66) 1872,1510 1840,1510 cw(c1839.99,1549.99) 1800,1550 1800,1975 cw(c1845,1975) 1845,2020 2180,2020 cw(c2180.02,1975.02) 2225,1975 2225,1694.99 ccw(c2279.98,1694.98) 2279.99,1640 2495,1640 ccw(c2495,1694.99)
G_A_HS on Top Layer "NONET_L-01_P-001" (solid, pour order 34): 3095,790 ccw(c3100,845) 3155,840 3155,865 3155,2065 3155,2075 ccw(c3100,2075) 3100,2130 3045,2130 cw(c3045,2175) 3000,2175 3000,2705 ccw(c2975,2705) 2975,2730 2655,2730 cw(c2655,2775) 2610,2775 2610,2830 cw(c2655,2830) 2655,2875 2670,2875 3250,2875 cw(c3250,2835) 3290,2835 3290,2820 3290,1270 ccw(c3345,1270) 3345,1215 3357.5,1215 3380,1215 cw(c3380,1170) 3425,1170 3425,1155 3425,510 3425,495 cw(c3380,494.99) 3380,450 3080,450 3060,450 cw(c3060,495) 3015,495 3015,745 cw(c3060,745) 3060,790 3085,790
G_B_LS on Top Layer "NONET_L-01_P-001" (solid, pour order 39): 2549.99,4694.99 cw(c2594.98,4694.99) 2595,4740 2975,4740 cw(c2972.51,4722.51) 2990,4720 2990,4680 cw(c2975.01,4679.99) 2975,4665 2865,4665 ccw(c2864.99,4635.01) 2835,4635 2835,4405 cw(c2790.01,4404.99) 2790,4360 2279.71,4360 ccw(c2279.69,4305.31) 2225,4305.29 2225,4035 cw(c2178.67,4036.33) 2180,3990 1865,3990 1845,3990 cw(c1844.99,4034.99) 1800,4035 1800,4205 cw(c1845,4205) 1845,4250 1874.71,4250 ccw(c1874.71,4305.29) 1930,4305.29 1930,4315 1930,4457.27 ccw(c1874.66,4454.66) 1872,4510 1840,4510 cw(c1839.99,4549.99) 1800,4550 1800,4975 cw(c1845,4975) 1845,5020 2180,5020 cw(c2180.02,4975.02) 2225,4975 2225,4694.99 ccw(c2279.98,4694.98) 2279.99,4640 2495,4640 ccw(c2495,4694.99)
G_B_HS on Top Layer "NONET_L-01_P-001" (solid, pour order 36): 3095,3790 ccw(c3100,3845) 3155,3840 3155,3865 3155,5065 3155,5075 ccw(c3100,5075) 3100,5130 3045,5130 cw(c3045,5175) 3000,5175 3000,5705 ccw(c2975,5705) 2975,5730 2655,5730 cw(c2655,5775) 2610,5775 2610,5830 cw(c2655,5830) 2655,5875 2670,5875 3250,5875 cw(c3250,5835) 3290,5835 3290,5820 3290,4270 ccw(c3345,4270) 3345,4215 3357.5,4215 3380,4215 cw(c3380,4170) 3425,4170 3425,4155 3425,3510 3425,3495 cw(c3380,3494.99) 3380,3450 3080,3450 3060,3450 cw(c3060,3495) 3015,3495 3015,3745 cw(c3060,3745) 3060,3790 3085,3790
S_A_LS on Top Layer "NONET_L-01_P-001" (solid, pour order 21): 2973.5,1650 cw(c2973.5,1635) 2988.5,1635 2988.5,1555 cw(c2973.5,1555) 2973.5,1540 2868.5,1540 cw(c2868.5,1555) 2853.5,1555 2853.5,1635 cw(c2868.5,1635) 2868.5,1650
S_A_LS on Top Layer "NONET_L-01_P-001" (solid, pour order 22): 2735,1650 cw(c2735,1635) 2750,1635 2750,1555 cw(c2735,1555) 2735,1540 2630,1540 cw(c2630,1555) 2615,1555 2615,1635 cw(c2630,1635) 2630,1650
AC_B on Top Layer "NONET_L-01_P-001" (solid, pour order 32): 200,5725 885,5725 ccw(c885,5780) 940,5780 940,7610 cw(c1035,7610) 1035,7705 1550,7705 ccw(c1550,7810) 1655,7810 1655,8220 cw(c1750,8220) 1750,8315 2815.01,8315 cw(c2815,8220) 2910,8219.99 2910,6590.02 cw(c2814.99,6590) 2815.01,6495 2254.99,6495 ccw(c2254.99,6390.01) 2150,6389.99 2150,5275 cw(c2057.53,5272.47) 2060,5180 1745.15,5180 ccw(c1745.12,5075.03) 1640.14,5075 1640.14,4904.86 cw(c1545.32,4904.83) 1545.29,4810 1265,4810 ccw(c1259.97,4705.03) 1155,4710 1155,3910 ccw(c1254.99,3909.99) 1255,3810 2060,3810 cw(c2057.52,3717.52) 2150,3715 2150,3464.71 cw(c2057.68,3462.32) 2060,3370 294.63,3370 cw(c294.66,3464.66) 200,3464.71
S_B_LS on Top Layer "NONET_L-01_P-001" (solid, pour order 37): 2973.5,4650 cw(c2973.5,4635) 2988.5,4635 2988.5,4555 cw(c2973.5,4555) 2973.5,4540 2868.5,4540 cw(c2868.5,4555) 2853.5,4555 2853.5,4635 cw(c2868.5,4635) 2868.5,4650
S_B_LS on Top Layer "NONET_L-01_P-001" (solid, pour order 38): 2735,4650 cw(c2735,4635) 2750,4635 2750,4555 cw(c2735,4555) 2735,4540 2630,4540 cw(c2630,4555) 2615,4555 2615,4635 cw(c2630,4635) 2630,4650
S_A_HS on Top Layer "NONET_L-01_P-001" (solid, pour order 42): 2630,2715 2965,2715 cw(c2965,2695) 2985,2695 2985,2655 cw(c2965.01,2654.99) 2965,2635 2630,2635 cw(c2630,2655) 2610,2655 2610,2695 cw(c2630,2695)
S_B_HS on Top Layer "NONET_L-01_P-001" (solid, pour order 43): 2630,5715 2965,5715 cw(c2965,5695) 2985,5695 2985,5655 cw(c2965.01,5654.99) 2965,5635 2630,5635 cw(c2630,5655) 2610,5655 2610,5695 cw(c2630,5695)
EGND on Top Layer "NONET_L-01_P-001" (solid, pour order 72): 4680,3700 ccw(c4680,3675) 4655,3675 4655,2325 ccw(c4680,2325) 4680,2300 4760,2300 ccw(c4760,2325) 4785,2325 4785,3675 ccw(c4760,3675) 4760,3700
DC+ on Layer 1 "NONET_L-01_P-001" (solid, pour order 48): 2320,2445 ccw(c2415,2445) 2415,2350 2551.88,2350 cw(c2555.07,2245.08) 2660,2248.23 2660,1805 ccw(c2754.99,1804.99) 2755,1710 2985,1710 cw(c2985.02,1605.02) 3090,1605 3090,1518.23 cw(c2984.81,1515.19) 2987.78,1410 2755,1410 ccw(c2754.97,1315.03) 2660,1315 2660,1260 cw(c2555.03,1259.97) 2555,1155 2393,1155 ccw(c2394.85,1081.43) 2321.28,1079.51 2320.01,294.99 ccw(c2414.98,294.98) 2415,200 4800,200 4800,7990 ccw(c4705,7990) 4705,8085 3885,8085 cw(c3884.99,8189.99) 3780,8190 3780,8555 ccw(c3685.01,8555.01) 3685,8650 3174.99,8650 ccw(c3175,8555) 3080,8554.99 3080,6435 cw(c2975,6435) 2975,6330 2415,6330 ccw(c2414.99,6235.01) 2320,6235 2320,5445 ccw(c2415,5444.99) 2415,5350 2555,5350 cw(c2555.02,5245.02) 2660,5245 2660,4805 ccw(c2754.99,4804.99) 2755,4710 2985,4710 cw(c2985.02,4605.02) 3090,4605 3090,4515 cw(c2985.03,4514.97) 2985,4410 2755,4410 ccw(c2754.97,4315.03) 2660,4315 2660,4260 cw(c2555.03,4259.97) 2555,4155 2415,4155 ccw(c2414.98,4060.03) 2320,4060
S_A_LS on Layer 1 "NONET_L-01_P-001" (solid, pour order 47): 2550,1695 cw(c2594.99,1694.99) 2595,1740 2965,1740 cw(c2965,1695.01) 3010,1695 3010,1405 cw(c2965.01,1404.99) 2965,1360 2279.71,1360 ccw(c2279.71,1305.29) 2225,1305.29 2225,1035 cw(c2178.65,1036.35) 2180,990 1865,990 1840,990 cw(c1842.5,1032.5) 1800,1035 1800,1205 cw(c1845,1205) 1845,1250 1874.71,1250 ccw(c1874.71,1305.29) 1930,1305.29 1930,1315 1930,1457.27 ccw(c1874.65,1454.65) 1872,1510 1840,1510 cw(c1840,1550) 1800,1550 1800,1975 cw(c1845,1975) 1845,2020 2180,2020 cw(c2180.01,1975.01) 2225,1975 2225,1695 ccw(c2280,1695) 2280,1640 2495,1640 ccw(c2495,1695)
S_A_HS on Layer 1 "NONET_L-01_P-001" (solid, pour order 40): 3095,790 ccw(c3100,845) 3155,840 3155,865 3155,2065 3155,2075 ccw(c3100,2075) 3100,2130 3045,2130 cw(c3045,2175) 3000,2175 3000,2600 ccw(c2975,2600) 2975,2625 2655,2625 cw(c2655,2670) 2610,2670 2610,2830 cw(c2655,2830) 2655,2875 2670,2875 3250,2875 cw(c3250,2835) 3290,2835 3290,2820 3290,1270 ccw(c3345,1270) 3345,1215 3357.5,1215 3380,1215 cw(c3380,1170) 3425,1170 3425,1155 3425,510 3425,495 cw(c3380.01,494.99) 3380,450 3080,450 3060,450 cw(c3060,495) 3015,495 3015,745 cw(c3060,745) 3060,790 3085,790
S_B_HS on Layer 1 "NONET_L-01_P-001" (solid, pour order 41): 3095,3790 ccw(c3100,3845) 3155,3840 3155,3865 3155,5065 3155,5075 ccw(c3100,5075) 3100,5130 3045,5130 cw(c3045,5175) 3000,5175 3000,5600 ccw(c2975,5600) 2975,5625 2655,5625 cw(c2655,5670) 2610,5670 2610,5830 cw(c2655,5830) 2655,5875 2670,5875 3250,5875 cw(c3250,5835) 3290,5835 3290,5820 3290,4270 ccw(c3345,4270) 3345,4215 3357.5,4215 3380,4215 cw(c3380,4170) 3425,4170 3425,4155 3425,3510 3425,3495 cw(c3380.01,3494.99) 3380,3450 3080,3450 3060,3450 cw(c3060,3495) 3015,3495 3015,3745 cw(c3060,3745) 3060,3790 3085,3790
S_B_LS on Layer 1 "NONET_L-01_P-001" (solid, pour order 29): 2550,4695 cw(c2594.99,4694.99) 2595,4740 2965,4740 cw(c2965,4695.01) 3010,4695 3010,4405 cw(c2965.01,4404.99) 2965,4360 2279.71,4360 ccw(c2279.71,4305.29) 2225,4305.29 2225,4035 cw(c2178.65,4036.35) 2180,3990 1865,3990 1840,3990 cw(c1842.5,4032.5) 1800,4035 1800,4205 cw(c1845,4205) 1845,4250 1874.71,4250 ccw(c1874.71,4305.29) 1930,4305.29 1930,4315 1930,4457.27 ccw(c1874.65,4454.65) 1872,4510 1840,4510 cw(c1840,4550) 1800,4550 1800,4975 cw(c1845,4975) 1845,5020 2180,5020 cw(c2180.01,4975.01) 2225,4975 2225,4695 ccw(c2280,4695) 2280,4640 2495,4640 ccw(c2495,4695)
AC_B on Layer 1 "NONET_L-01_P-001" (solid, pour order 51): 885,5725 ccw(c885.14,5779.86) 940,5779.71 940,7610 cw(c1034.99,7610) 1035,7705 1055,7704.99 1435,7705 1550,7705 ccw(c1550,7810) 1655,7810 1655,8220 cw(c1749.93,8220) 1749.93,8314.93 2815.07,8314.93 cw(c2815.07,8220) 2910,8220 2910,6590 cw(c2815.01,6589.99) 2815,6495 2255,6495 ccw(c2254.99,6390.01) 2150,6390 2150,5275 cw(c2057.53,5272.47) 2060,5180 1745.15,5180 ccw(c1745.12,5075.03) 1640.14,5075 1640.14,4904.86 cw(c1545.31,4904.83) 1545.29,4810 1265,4810 ccw(c1259.97,4705.03) 1155,4710 1155,3910 ccw(c1254.99,3909.99) 1255,3810 2055,3810 cw(c2055.02,3715.02) 2150,3715 2150,3464.71 cw(c2055.17,3464.83) 2055,3370 294.63,3370 cw(c294.66,3464.66) 200,3464.71 200,5725
AC_A on Layer 1 "NONET_L-01_P-001" (solid, pour order 60): 200,2655 cw(c295,2655) 295,2750 350,2750 2000,2750 2055,2750 cw(c2055,2655) 2150,2655 2150,2600 2150,2274.99 cw(c2055.04,2274.96) 2055,2180 1745.15,2180 ccw(c1745.1,2075.04) 1640.14,2075 1640.14,1904.86 cw(c1545.33,1904.81) 1545.29,1810 1265,1810 ccw(c1259.95,1705.05) 1155,1710 1155,910 ccw(c1254.98,909.98) 1255,810 2055,810 cw(c2055.03,715.03) 2150,715 2150,535 cw(c2055.05,534.95) 2055,440 1072.65,440 cw(c1058.66,928.66) 570,914.72 570,1620 ccw(c465.01,1620.01) 465,1725 300,1725 cw(c299.98,1824.98) 200,1825
GND on Layer 1 "NONET_L-01_P-001" (solid, pour order 66): 335,8035 625,8035 cw(c625.01,7940.01) 720,7940 720,6310 cw(c625.01,6309.99) 625,6215 335,6215 cw(c335,6309.94) 240.05,6309.95 240.05,7940.05 cw(c335,7940.05)
DC- on Layer 4 "NONET_L-01_P-001" (solid, pour order 73): 3080,7430 3080,7590 cw(c3175,7590) 3175,7685 3300,7685 3614.93,7685 ccw(c3615.01,7789.99) 3720,7789.93 3720,7825 3720,8555 cw(c3815,8555) 3815,8650 3885,8650 4800,8650 4800,200 2440,200 2415,200 cw(c2415,295) 2320,295 2320,6235 cw(c2414.99,6235) 2414.99,6329.99 2975,6330.01 ccw(c2975,6435) 3080,6435
+5V on Layer 4 "NONET_L-01_P-001" (solid, pour order 69): 335,8035 625,8035 cw(c625.01,7940.01) 720,7940 720,6310 cw(c625.01,6309.99) 625,6215 335,6215 cw(c335,6309.94) 240.05,6309.95 240.05,7940.05 cw(c335,7940.05)
AC_A on Layer 4 "NONET_L-01_P-001" (solid, pour order 74): 1155,3910 ccw(c1254.98,3909.98) 1255,3810 1580,3810 cw(c1580,3715.41) 1674.59,3715.41 1675,3715 1675,3465 ccw(c1779.99,3464.99) 1780,3360 2055,3360 cw(c2055,3265.02) 2150,3265 2150,2274.99 cw(c2055.03,2274.97) 2055,2180 1745.15,2180 ccw(c1745.11,2075.03) 1640.14,2075 1640.14,1904.86 cw(c1545.32,1904.82) 1545.29,1810 1265,1810 ccw(c1259.96,1705.04) 1155,1710 1155,910 ccw(c1254.98,909.98) 1255,810 2055,810 cw(c2055.02,715.03) 2150,715 2150,535 cw(c2055.04,534.96) 2055,440 1072.65,440 cw(c1058.66,928.66) 570,914.72 570,1620 ccw(c465.01,1620) 465,1725 300,1725 cw(c299.98,1824.98) 200,1825 200,4110 200,5725 885,5725 ccw(c885,5780) 940,5779.99 940,8219.99 cw(c1035,8220) 1034.99,8315 2055,8315 cw(c2055,8220) 2150,8220 2149.99,5741.01 cw(c2055.03,5739.97) 2055,5645 1750.14,5645 ccw(c1750.12,5535.03) 1640.14,5535 1640.14,4904.86 cw(c1545.32,4904.83) 1545.29,4810 1260,4810 ccw(c1259.97,4705.03) 1155,4705
DC- on Layer 2 "NONET_L-01_P-001" (solid, pour order 45): 3080,7430 3080,7590 cw(c3175,7590) 3175,7685 3300,7685 3614.93,7685 ccw(c3615.01,7789.99) 3720,7789.93 3720,7825 3720,8555 cw(c3815,8555) 3815,8650 3885,8650 4800,8650 4800,200 2440,200 2415,200 cw(c2415,295) 2320,295 2320,6235 cw(c2414.99,6235) 2414.99,6329.99 2975,6330.01 ccw(c2975,6435) 3080,6435
+5V on Layer 2 "NONET_L-01_P-001" (solid, pour order 67): 335,8035 625,8035 cw(c625.01,7940.01) 720,7940 720,6310 cw(c625.01,6309.99) 625,6215 335,6215 cw(c335,6309.94) 240.05,6309.95 240.05,7940.05 cw(c335,7940.05)
AC_A on Layer 2 "NONET_L-01_P-001" (solid, pour order 71): 200,2655 cw(c295,2655) 295,2750 350,2750 2000,2750 2055,2750 cw(c2055,2655) 2150,2655 2150,2600 2150,2274.99 cw(c2055.04,2274.96) 2055,2180 1745.15,2180 ccw(c1745.1,2075.04) 1640.14,2075 1640.14,1904.86 cw(c1545.33,1904.81) 1545.29,1810 1265,1810 ccw(c1259.95,1705.05) 1155,1710 1155,910 ccw(c1254.98,909.98) 1255,810 2055,810 cw(c2055.03,715.03) 2150,715 2150,535 cw(c2055.05,534.95) 2055,440 1072.65,440 cw(c1058.66,928.66) 570,914.72 570,1620 ccw(c465.01,1620.01) 465,1725 300,1725 cw(c299.98,1824.98) 200,1825
DC+ on Bottom Layer "NONET_L-01_P-001" (solid, pour order 46): 2320,2475 ccw(c2409.99,2474.99) 2410,2385 2595,2385 cw(c2595.02,2285.03) 2695,2285 2695,1840 ccw(c2794.98,1839.98) 2795,1740 3020,1740 cw(c3020.02,1640.03) 3120,1640 3120,1480 cw(c3000.04,1494.94) 2985,1375 2790,1375 ccw(c2789.96,1280.04) 2695,1280 2695,1220 cw(c2590.05,1219.95) 2590,1115 2365,1115 ccw(c2364.97,1070.03) 2320,1070 2320,285 ccw(c2404.98,284.98) 2405,200 4800,200 4800,7600 ccw(c4705,7600) 4705,7695 3855,7695 cw(c3855,7800) 3750,7800 3750,8555 ccw(c3655,8555) 3655,8650 3175,8650 ccw(c3175,8555) 3080,8555 3080,6435 cw(c2975,6435) 2975,6330 2415,6330 ccw(c2415,6235) 2320,6235 2320,5485 ccw(c2419.99,5484.99) 2420,5385 2590,5385 cw(c2590.03,5280.03) 2695,5280 2695,4845 ccw(c2794.99,4844.99) 2795,4745 3020,4745 cw(c3000.04,4625.03) 3120,4605 3120,4480 cw(c3015.05,4479.95) 3015,4375 2790,4375 ccw(c2789.95,4280.05) 2695,4280 2695,4225 cw(c2590.05,4224.95) 2590,4120 2365,4120 ccw(c2364.97,4075.03) 2320,4075
AC_A on Bottom Layer "NONET_L-01_P-001" (solid, pour order 55): 2055,2750 cw(c2055,2655) 2150,2655 2150,2274.99 cw(c2055.04,2274.96) 2055,2180 1745.15,2180 ccw(c1745.1,2075.04) 1640.14,2075 1640.14,1904.86 cw(c1545.33,1904.82) 1545.29,1810 1265,1810 ccw(c1259.96,1705.04) 1155,1710 1155,910 ccw(c1254.99,909.99) 1255,810 2055,810 cw(c2055.03,715.03) 2150,715 2150,535 cw(c2055.04,534.96) 2055,440 695,440 cw(c694.99,534.99) 600,534.98 600,1010 cw(c695,1010) 695,1105 960,1105 ccw(c960,1210) 1065,1210 1065,1505 ccw(c960.01,1505.01) 960,1610 630,1610 cw(c630,1655) 585,1655 585,1700.62 ccw(c528.93,1703.92) 532.22,1760 295,1760 cw(c295,1855) 200,1855 200,2750
DC+ on Layer 3 "NONET_L-01_P-001" (solid, pour order 44): 2320,2445 ccw(c2415,2445) 2415,2350 2551.88,2350 cw(c2555.07,2245.07) 2660,2248.23 2660,1805 ccw(c2754.99,1804.99) 2755,1710 2985,1710 cw(c2985.01,1605.02) 3090,1605 3090,1518.23 cw(c2984.8,1515.2) 2987.78,1410 2755,1410 ccw(c2754.98,1315.02) 2660,1315 2660,1260 cw(c2555.03,1259.97) 2555,1155 2320,1155 2320,295 ccw(c2415,295) 2415,200 4800,200 4800,7990 ccw(c4705,7990) 4705,8085 3885,8085 cw(c3885,8190) 3780,8190 3780,8555 ccw(c3685,8555) 3685,8650 3175.08,8650 ccw(c3174.99,8554.99) 3079.98,8555.08 3080,8085 3080,6435.43 cw(c2974.58,6435.42) 2974.58,6330 2415,6330 ccw(c2414.99,6235.01) 2320,6235 2320,5445.01 ccw(c2415,5445) 2415,5350 2555,5350 cw(c2555.01,5245.01) 2660,5245 2660,4805 ccw(c2755,4805) 2755,4710 2985,4710 cw(c2985.01,4605.01) 3090,4605 3090,4515 cw(c2985.02,4514.98) 2985,4410 2755,4410 ccw(c2754.99,4315.02) 2660,4315 2660,4260 cw(c2555.02,4259.98) 2555,4155 2320,4155
AC_A on Layer 3 "NONET_L-01_P-001" (solid, pour order 58): 1155,3910 ccw(c1254.98,3909.98) 1255,3810 1580,3810 cw(c1580,3715.41) 1674.59,3715.41 1675,3715 1675,3465 ccw(c1779.99,3464.99) 1780,3360 2055,3360 cw(c2055,3265.02) 2150,3265 2150,2274.99 cw(c2055.03,2274.97) 2055,2180 1745.15,2180 ccw(c1745.11,2075.03) 1640.14,2075 1640.14,1904.86 cw(c1545.32,1904.82) 1545.29,1810 1265,1810 ccw(c1259.96,1705.04) 1155,1710 1155,910 ccw(c1254.98,909.98) 1255,810 2055,810 cw(c2055.02,715.03) 2150,715 2150,535 cw(c2055.04,534.96) 2055,440 1072.65,440 cw(c1058.66,928.66) 570,914.72 570,1620 ccw(c465.01,1620) 465,1725 300,1725 cw(c299.98,1824.98) 200,1825 200,4110 200,5725 885,5725 ccw(c885,5780) 940,5779.99 940,8219.99 cw(c1035,8220) 1034.99,8315 2055,8315 cw(c2055,8220) 2150,8220 2149.99,5741.01 cw(c2055.03,5739.97) 2055,5645 1750.14,5645 ccw(c1750.12,5535.03) 1640.14,5535 1640.14,4904.86 cw(c1545.32,4904.83) 1545.29,4810 1260,4810 ccw(c1259.97,4705.03) 1155,4705
GND on Layer 3 "NONET_L-01_P-001" (solid, pour order 68): 335,8035 625,8035 cw(c625.01,7940.01) 720,7940 720,6310 cw(c625.01,6309.99) 625,6215 335,6215 cw(c335,6309.94) 240.05,6309.95 240.05,7940.05 cw(c335,7940.05)

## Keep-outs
Top Layer:
  rectangle: 3930,6595 4320,6810
  rectangle: 3930,3995 4320,4210
  rectangle: 3930,1395 4320,1610
  rectangle: 2496.34,5960.21 2561.34,6010.21
  rectangle: 2496.34,2960.21 2561.34,3010.21
  rectangle: 2800,3360 2940,3420
  rectangle: 2688.32,4755 2821.68,4943.45
  rectangle: 2688.32,1755 2821.68,1943.45
  rectangle: 3720,4575 3815,4815
  rectangle: 3720,1575 3815,1815
  lines w10: 195,5348 cw(c245,5348) 245,5398 ; 598.02,5697.1 cw(c645,5680) 645,5730 ; 1805,3365 ccw(c1805,3415) 1855,3415 ; 1885,3415 ccw(c1935,3415) 1935,3365 ; 2315,1700 ccw(c2365,1700) 2365,1650 ; 2315,4300 cw(c2365,4300) 2365,4350 ; 2315,4700 ccw(c2365,4700) 2365,4650 ; 2453.59,5506.06 2455,5930 cw(c2555,5930) 2555,6030 ; 2454.69,2837.56 2455,2930 cw(c2555,2930) 2555,3030 ; 2557.53,3029.82 2647.44,3030.06 ; 2557.53,6029.82 2647.44,6030.06 ; 2593,1750 ccw(c2593,1850) 2693,1850 ; 2593,4750 ccw(c2593,4850) 2693,4850 ; 2635,5265 2795,5265 cw(c2795,5215) 2845,5215 ; 2764.42,3370 3027.4,3297.1 ; 2795,2265 cw(c2795,2215) 2845,2215 ; 2812,3730 ccw(c2812,3780) 2862,3780 ; 2812.1,2113.02 ccw(c2795,2160) 2845,2160 ; 2812.1,5113.02 ccw(c2795,5160) 2845,5160 ; 2845,4480 cw(c2895,4480) 2895,4530 ; 2847.1,3876.98 cw(c2830,3830) 2880,3830 ; 2900,4245 ccw(c2900,4345) 3000,4345 ; 2950,4530 cw(c2950,4480) 3000,4480 ; 3445,2170 ccw(c3545,2170) 3545,2070 ; 3445,2230 cw(c3545,2230) 3545,2330 ; 3445,2820 ccw(c3545,2820) 3545,2720 ; 3445,5170 ccw(c3545,5170) 3545,5070 ; 3445,5230 cw(c3545,5230) 3545,5330 ; 3445,5820 ccw(c3545,5820) 3545,5720 ; 3580,1190 cw(c3630,1190) 3612.9,1236.98 ; 3580,4190 cw(c3630,4190) 3612.9,4236.98 ; 3814,1875 3815.62,1484.43 ; 3814,4875 3815.62,4484.43 ; 4300,195 ccw(c4300,295) 4400,295 ; 4302,8655 cw(c4302,8555) 4402,8555
Layer 1:
  circle w15: c3501,5525 r47.17
  circle w15: c3619,5525 r47.17
  circle w15: c3619,2525 r47.17
  circle w15: c3501,2525 r47.17
  rectangle: 3965,2695 4285,2910
  rectangle: 3965,5295 4285,5510
  rectangle: 3416,2460 3450,2585
  rectangle: 3416,5460 3450,5585
  rectangle: 3500,5470 3620,5580
  rectangle: 3500,2470 3620,2580
  region: 3335.22,4875 3784.78,4875 3816.99,4546.5 3269.63,4546.5
  region: 3335.22,1875 3784.78,1875 3816.99,1546.5 3269.63,1546.5
  lines w10: 195,2585 cw(c295,2585) 295,2685 ; 195,5335 cw(c295,5335) 295,5435 ; 556.22,5663.89 cw(c635,5650) 635,5730 ; 625,7045.79 cw(c625,6945.79) 725,6945.79 ; 625,7495 ccw(c625,7595) 725,7595 ; 2315,562 cw(c2415,562) 2415,662 ; 2315,3562 cw(c2415,3562) 2415,3662 ; 2344,1007 ccw(c2394,1007) 2394,957 ; 2344,4007 ccw(c2394,4007) 2394,3957 ; 2346,1110 cw(c2396,1110) 2396,1160 ; 2346,4110 cw(c2396,4110) 2396,4160 ; 2623.02,2471.1 cw(c2670,2454) 2670,2504 ; 2623.02,5471.1 cw(c2670,5454) 2670,5504 ; 2643.7,1214 cw(c2687,1189) 2687,1239 ; 2643.7,4214 cw(c2687,4189) 2687,4239 ; 2655,1960 ccw(c2755,1960) 2755,1860 ; 2655,4960 ccw(c2755,4960) 2755,4860 ; 2779,2504 cw(c2779,2404) 2879,2404 ; 2779,5504 cw(c2779,5404) 2879,5404 ; 2934,1239 cw(c2934,1139) 3034,1139 ; 2934,4239 cw(c2934,4139) 3034,4139 ; 2985,1860 ccw(c2985,1910) 3035,1910 ; 2985,4860 ccw(c2985,4910) 3035,4910 ; 3002.1,2014.98 cw(c2985,1968) 3035,1968 ; 3002.1,5014.98 cw(c2985,4968) 3035,4968 ; 3009,902.7 ccw(c2984,946) 3034,946 ; 3009,3902.7 ccw(c2984,3946) 3034,3946 ; 3411,2135 ccw(c3511,2135) 3511,2035 ; 3411,2376 cw(c3511,2376) 3511,2476 ; 3411,5135 ccw(c3511,5135) 3511,5035 ; 3411,5376 cw(c3511,5376) 3511,5476 ; 3435,2675 ccw(c3535,2675) 3535,2575 ; 3435,5675 ccw(c3535,5675) 3535,5575 ; 3545,1183 cw(c3595,1183) 3595,1233 ; 3545,4183 cw(c3595,4183) 3595,4233 ; 3870,195 ccw(c3870,295) 3970,295 ; 4275,275 ccw(c4355,275) 4355,195 ccw(c4355,275) 4435,275 ; 4705,565 ccw(c4705,665) 4805,665 ; 4705,2685 cw(c4705,2585) 4805,2585 ; 4705,3315 ccw(c4705,3415) 4805,3415 ; 4705,5435 cw(c4705,5335) 4805,5335 ; 4705,6065 ccw(c4705,6165) 4805,6165
Layer 4:
  region: 2148.23,6965 2148.23,7578.68 2117.62,7578.68 2117.62,6965
  region: 2146.02,7015 2146.02,7525 2060,7525 2060,7015
  rectangle: 3965,6595 4285,6810
  rectangle: 3965,1395 4285,1610
  rectangle: 3965,3995 4285,4210
  region: 3335.22,1875 3784.78,1875 3816.99,1546.5 3269.63,1546.5
  region: 3335.22,4875 3784.78,4875 3816.99,4546.5 3269.63,4546.5
  lines w10: 195,2585 cw(c295,2585) 295,2685 ; 195,3415 ccw(c295,3415) 295,3315 ; 195,5335 cw(c295,5335) 295,5435 ; 556.22,5663.89 cw(c635,5650) 635,5730 ; 625,7045.79 cw(c625,6945.79) 725,6945.79 ; 625,7495 ccw(c625,7595) 725,7595 ; 1955,7045.79 cw(c1955,6845.79) 2155,6845.79 ; 1955,7495 ccw(c1955,7695) 2155,7695 ; 2564.2,2582.03 ccw(c2530,2676) 2630,2676 ; 2564.2,5582.03 ccw(c2530,5676) 2630,5676 ; 2900,2420 2951,2653.51 ; 2900,5420 2951,5653.51 ; 4335,195 ccw(c4335,295) 4435,295 ; 4335,8655 cw(c4335,8555) 4435,8555 ; 4705,1000 ccw(c4705,1100) 4805,1100 ; 4705,2685 cw(c4705,2585) 4805,2585 ; 4705,3315 ccw(c4705,3415) 4805,3415 ; 4705,5000 cw(c4705,4900) 4805,4900 ; 4705,6065 ccw(c4705,6165) 4805,6165 ; 4705,6370 cw(c4705,6270) 4805,6270 ; 4705,6650 ccw(c4705,6750) 4805,6750 ; 4705,8185 cw(c4705,8085) 4805,8085 ; 4735,568 ccw(c4735,638) 4805,638 ; 4735,720 cw(c4735,650) 4805,650 ; 4735,5280 ccw(c4735,5350) 4805,5350 ; 4735,5432 cw(c4735,5362) 4805,5362
Layer 2:
  rectangle: 3965,6595 4285,6810
  rectangle: 3965,3995 4285,4210
  rectangle: 3965,1395 4285,1610
  region: 3335.22,4875 3784.78,4875 3816.99,4546.5 3269.63,4546.5
  region: 3335.22,1875 3784.78,1875 3816.99,1546.5 3269.63,1546.5
  lines w10: 195,2585 cw(c295,2585) 295,2685 ; 625,7045.79 cw(c625,6945.79) 725,6945.79 ; 625,7495 ccw(c625,7595) 725,7595 ; 2564.2,2582.03 ccw(c2530,2676) 2630,2676 ; 2564.2,5582.03 ccw(c2530,5676) 2630,5676 ; 2900,2420 2951,2653.51 ; 2900,5420 2951,5653.51 ; 4335,195 ccw(c4335,295) 4435,295 ; 4335,8655 cw(c4335,8555) 4435,8555 ; 4705,1000 ccw(c4705,1100) 4805,1100 ; 4705,2685 cw(c4705,2585) 4805,2585 ; 4705,3315 ccw(c4705,3415) 4805,3415 ; 4705,5000 cw(c4705,4900) 4805,4900 ; 4705,6065 ccw(c4705,6165) 4805,6165 ; 4705,6370 cw(c4705,6270) 4805,6270 ; 4705,6650 ccw(c4705,6750) 4805,6750 ; 4705,8185 cw(c4705,8085) 4805,8085 ; 4735,568 ccw(c4735,638) 4805,638 ; 4735,720 cw(c4735,650) 4805,650 ; 4735,5280 ccw(c4735,5350) 4805,5350 ; 4735,5432 cw(c4735,5362) 4805,5362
